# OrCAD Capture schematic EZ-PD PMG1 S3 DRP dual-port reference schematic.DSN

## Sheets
1 01 TABLE AND CONTENTS: title: PMG1-S3 (CYPM1322) 97BGA DRP REF DESIGN; rev: 01; note: XXX-xxxxx-xx
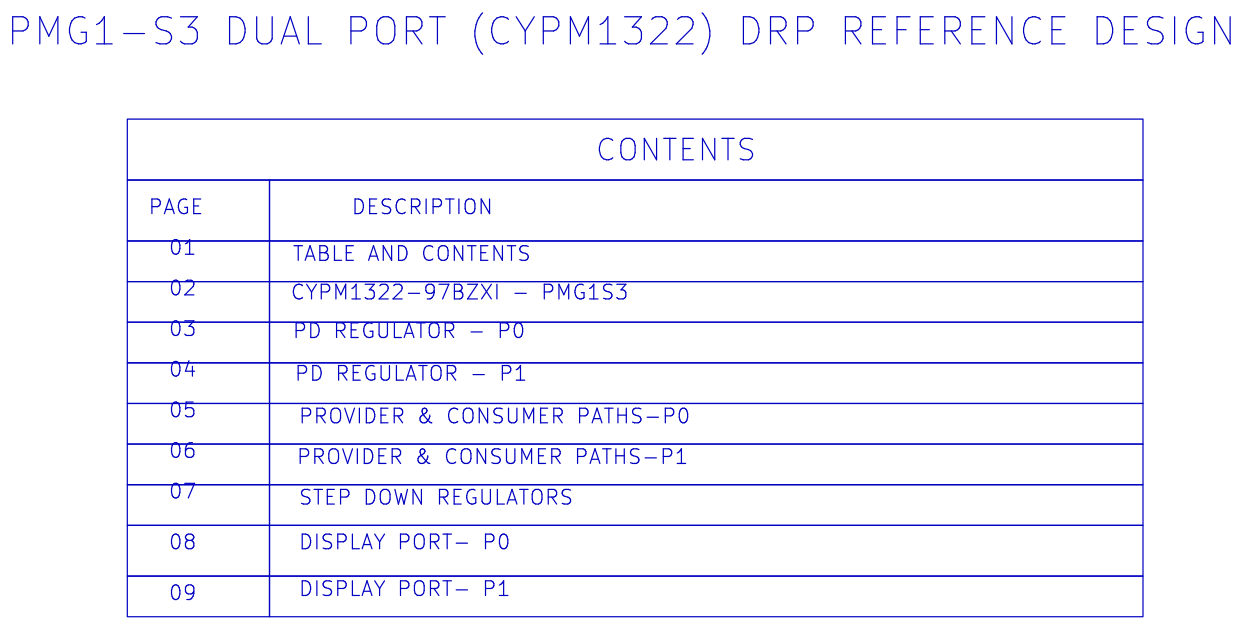
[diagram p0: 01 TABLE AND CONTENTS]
2 02  CYPM1322-97BZXI - PMG1S3: size A4
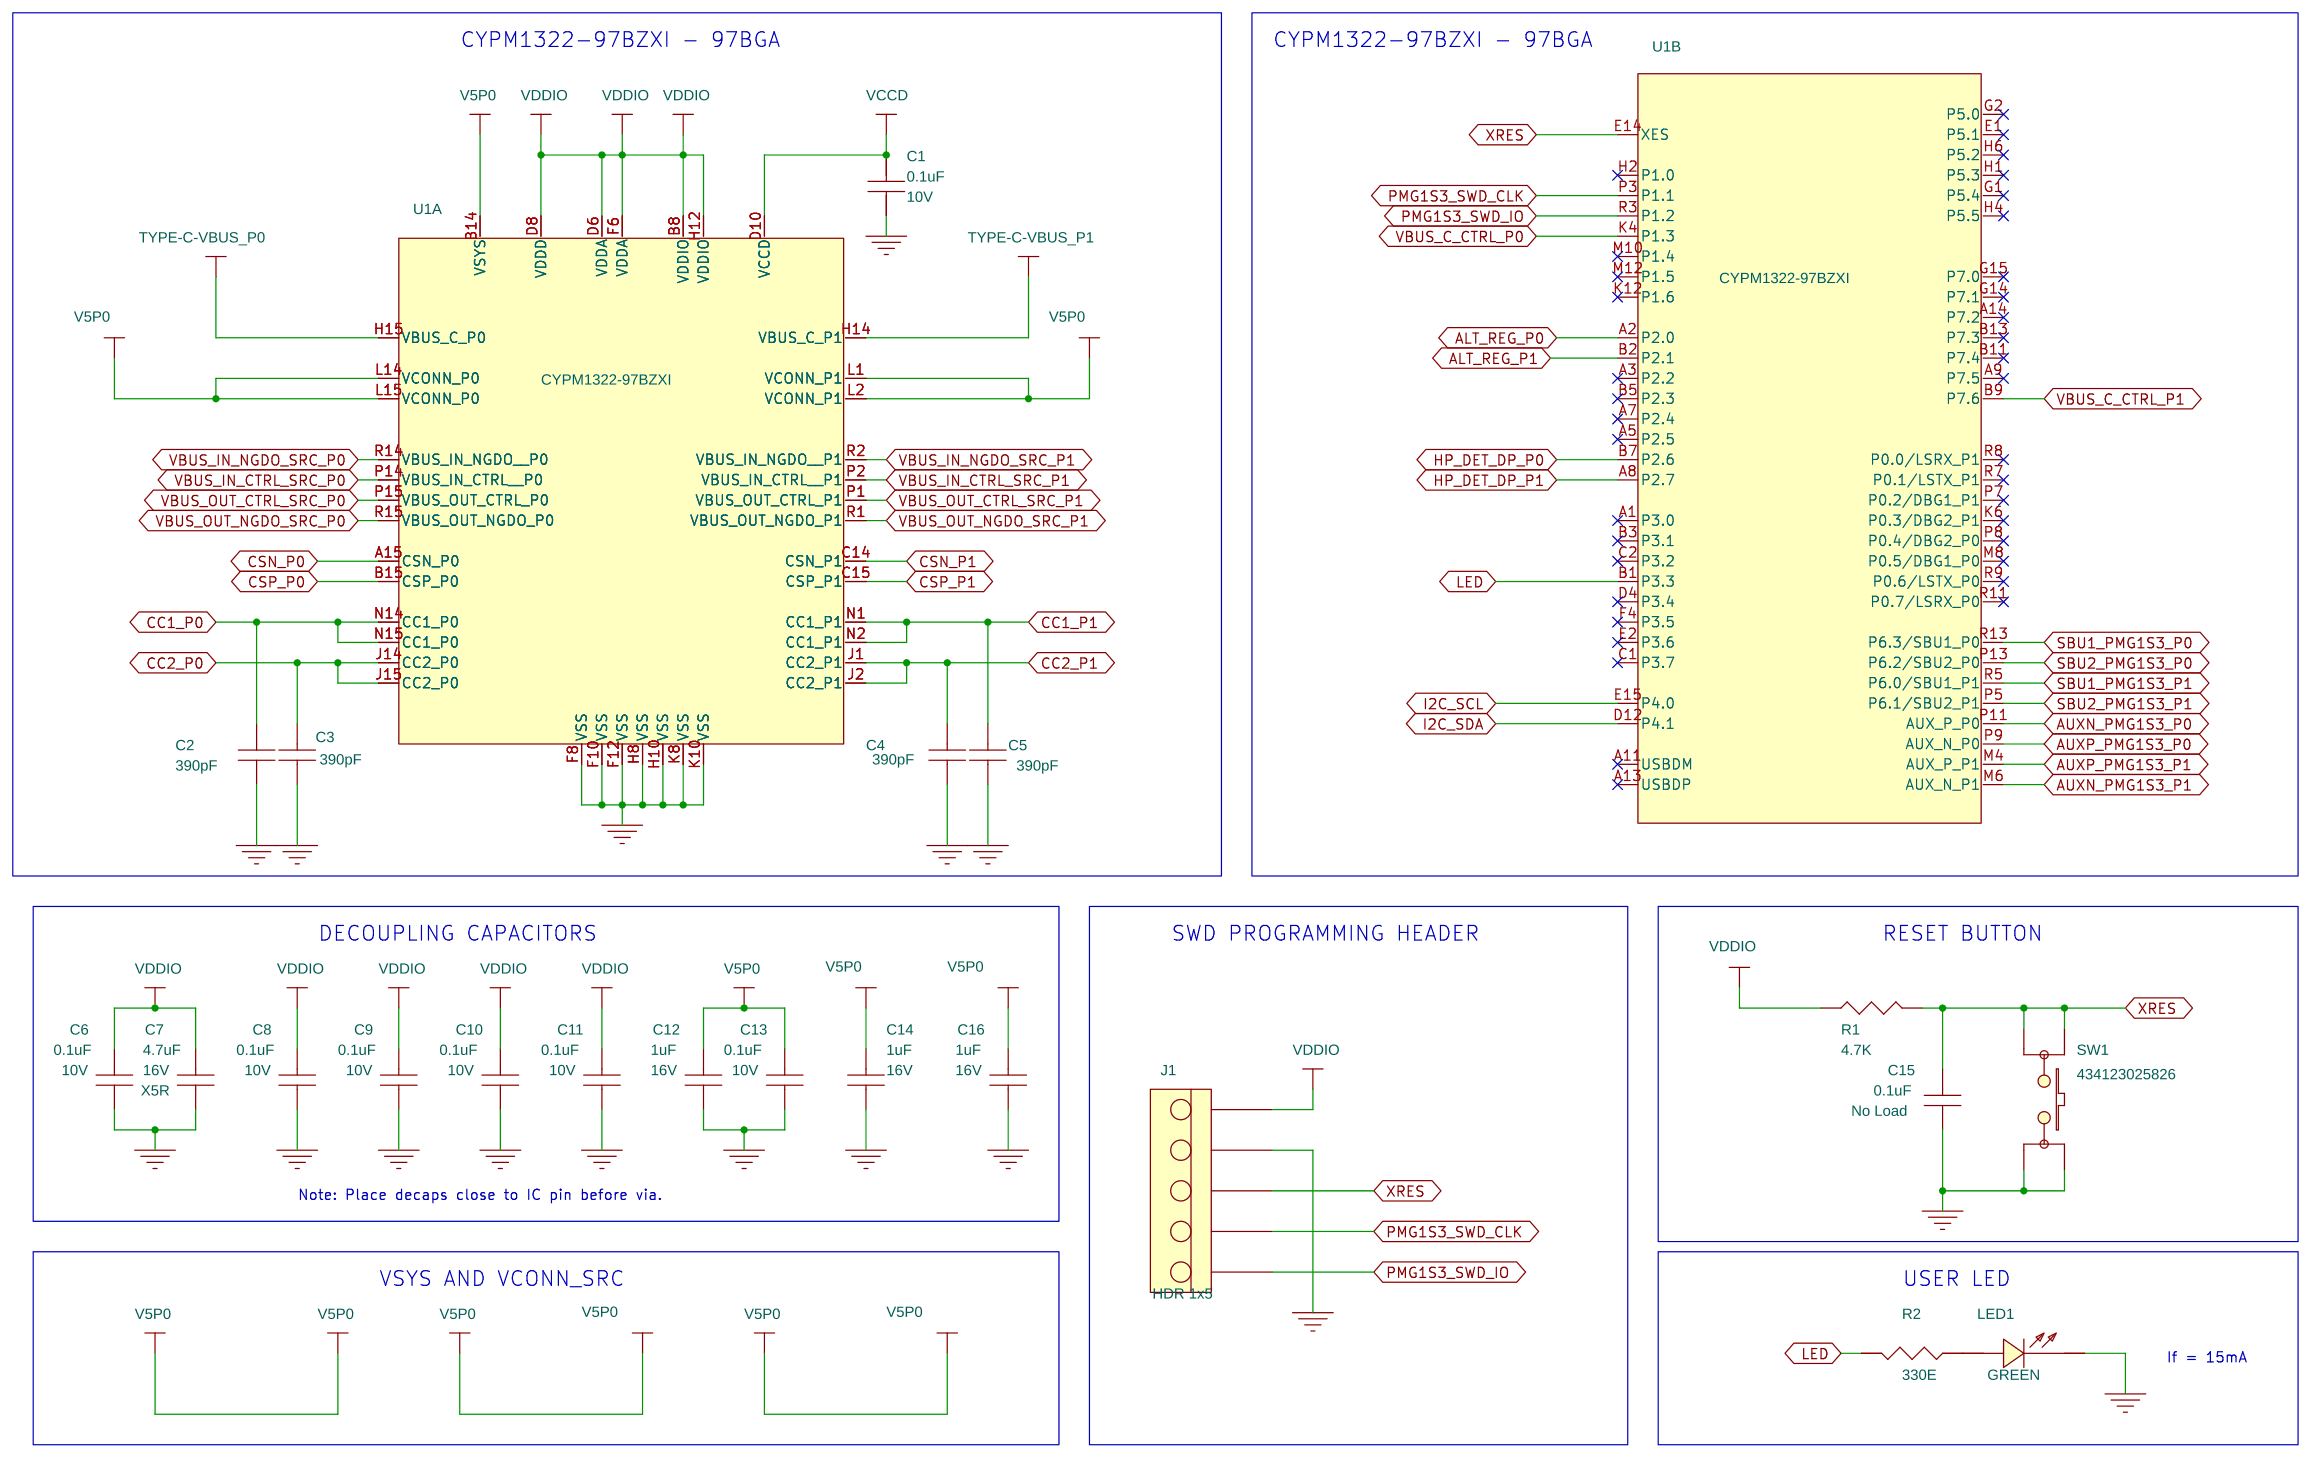
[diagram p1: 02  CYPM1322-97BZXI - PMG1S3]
3 03 PD REGULATOR - P0: size A4
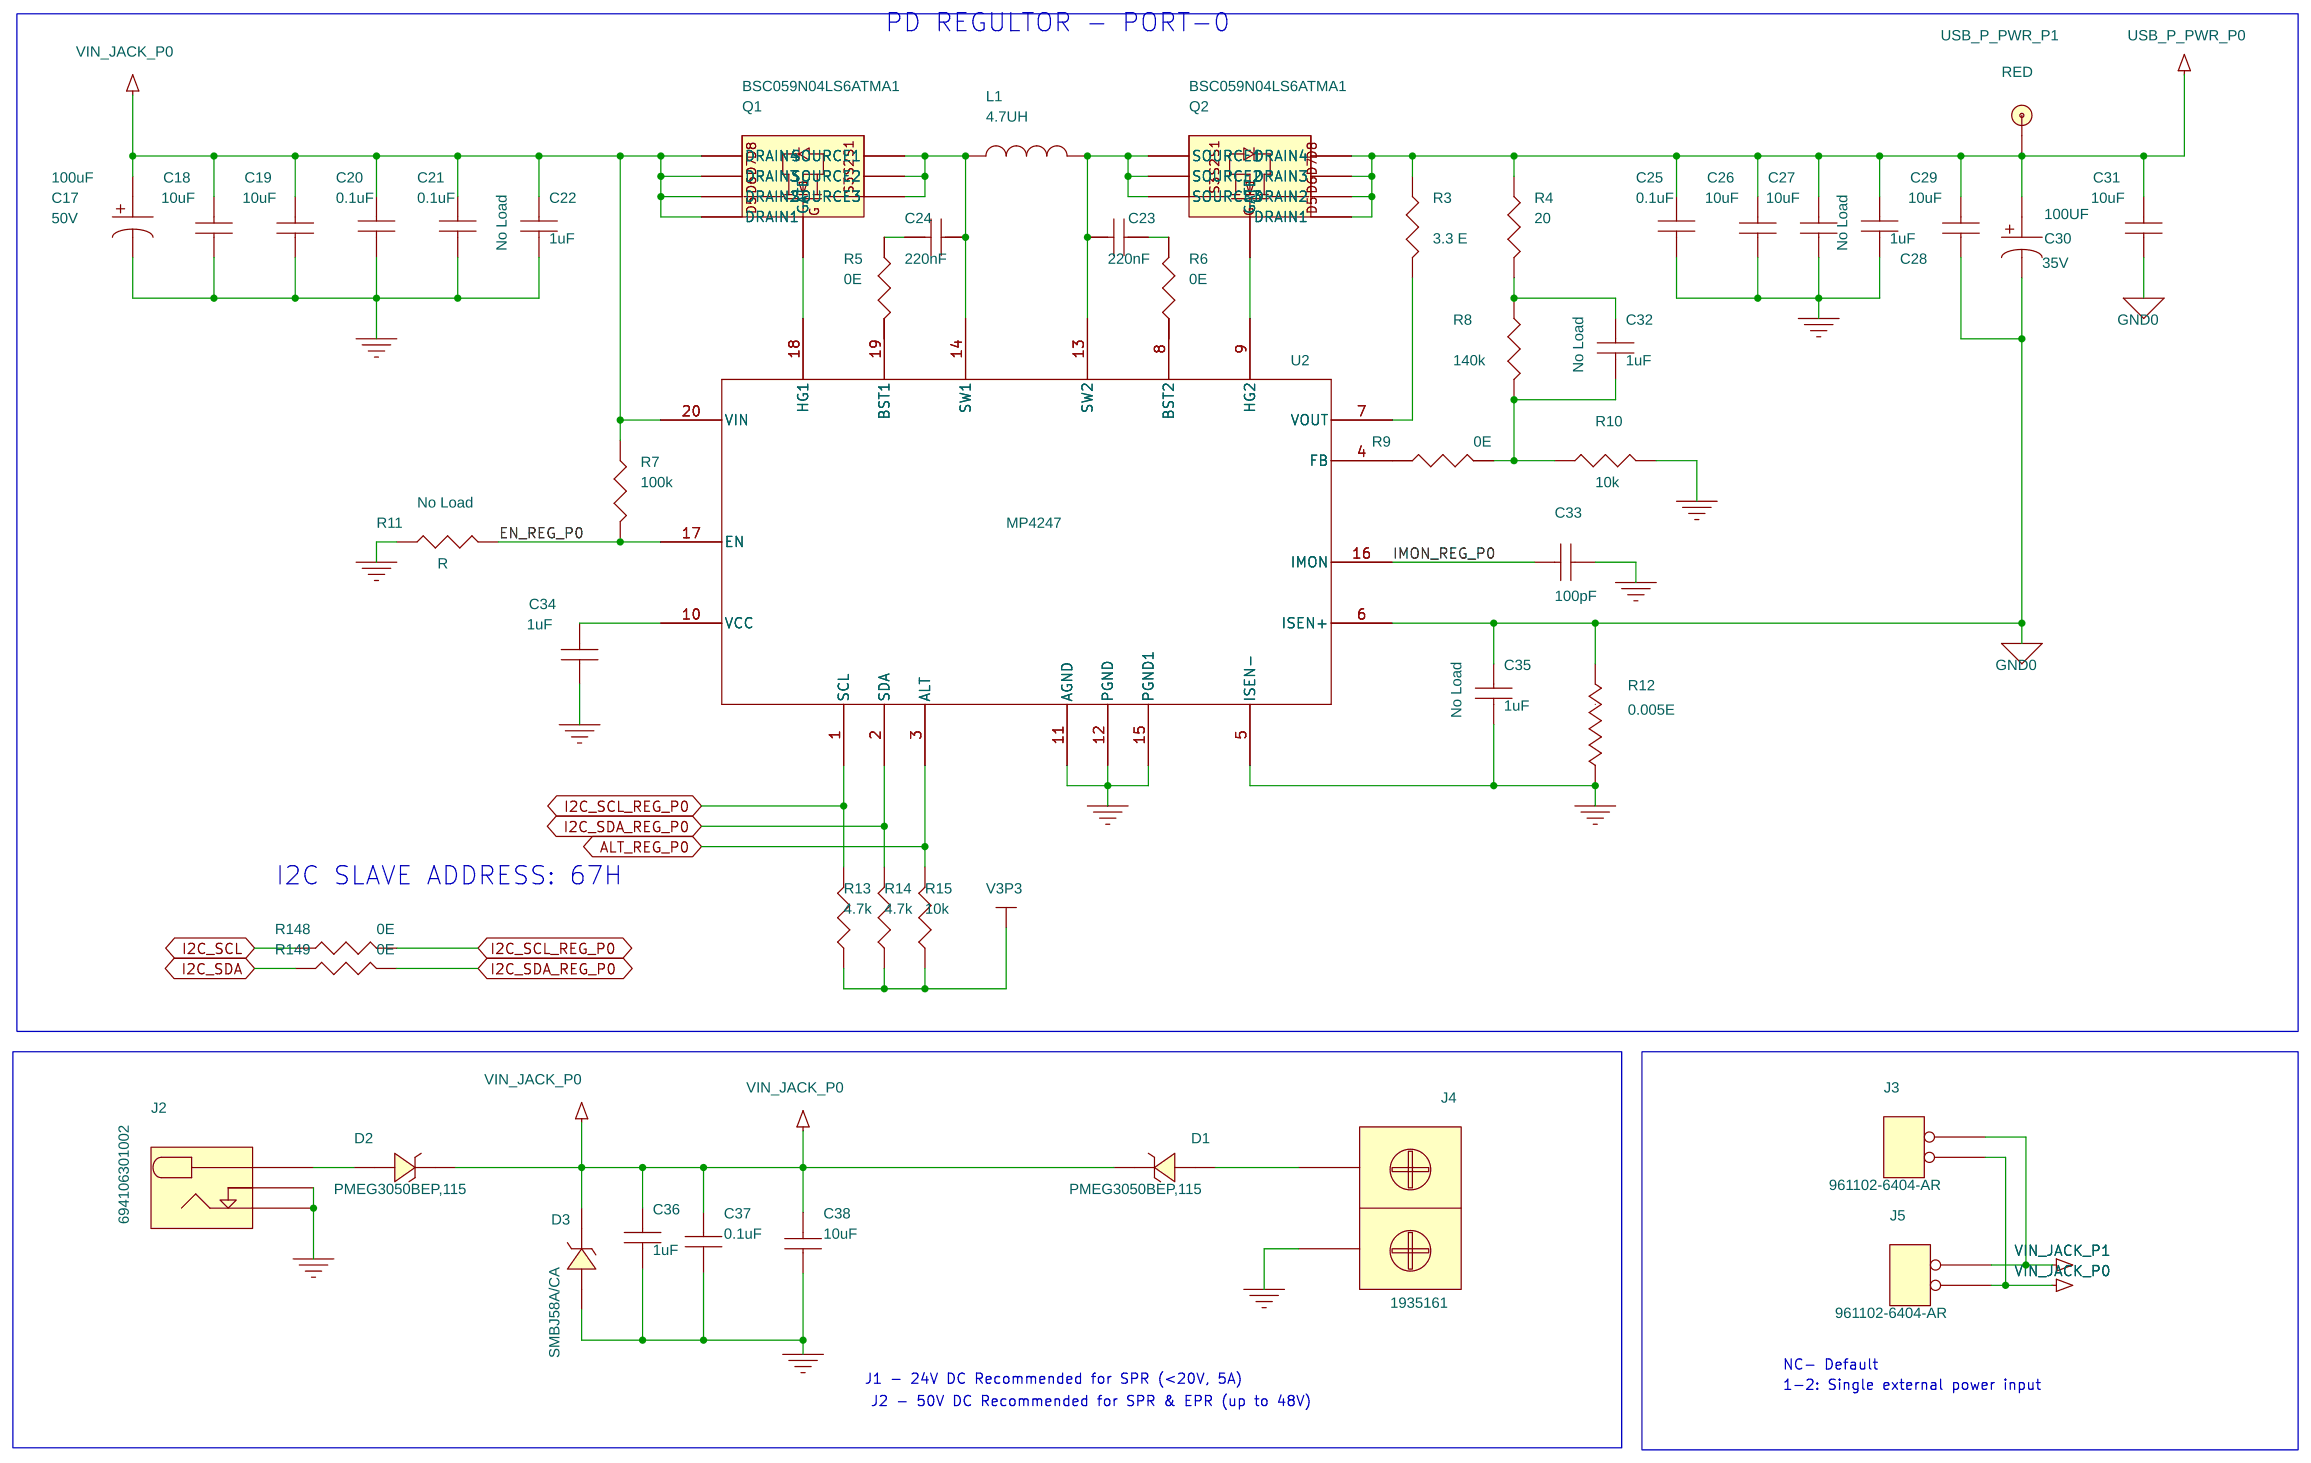
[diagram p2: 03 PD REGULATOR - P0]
4 04 PD REGULATROR - P1: size A4
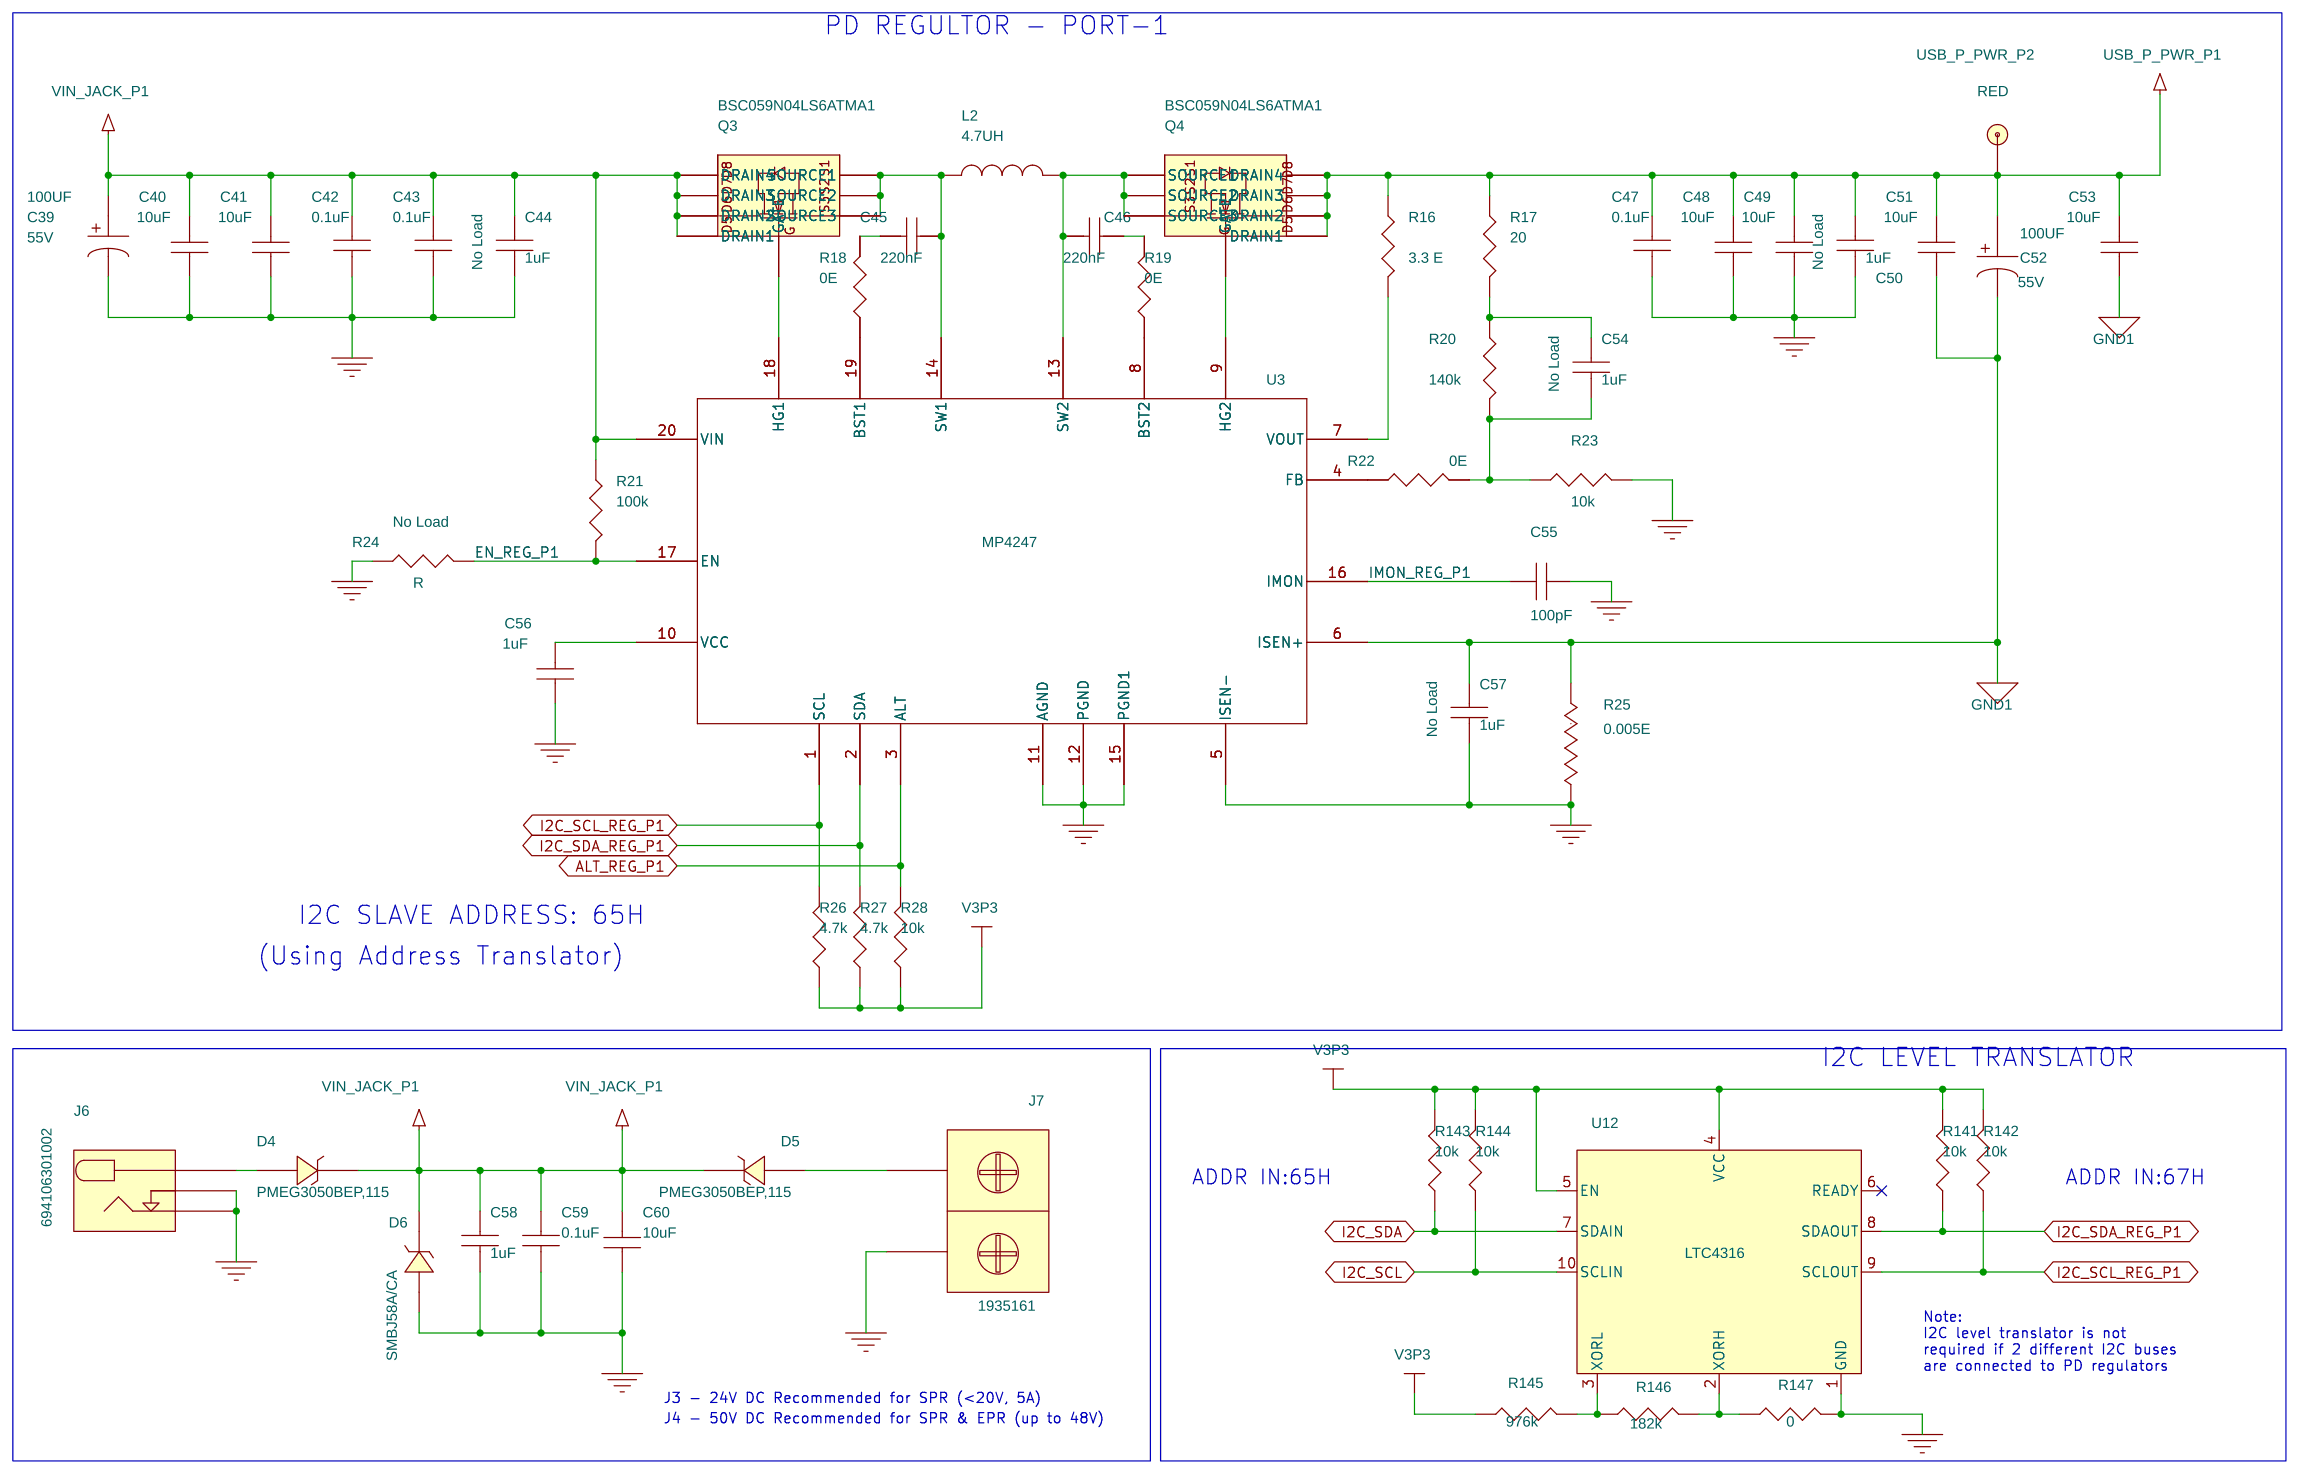
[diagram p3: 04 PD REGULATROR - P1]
5 05 PROVIDER & CONSUMER PATHS-P0: size A4
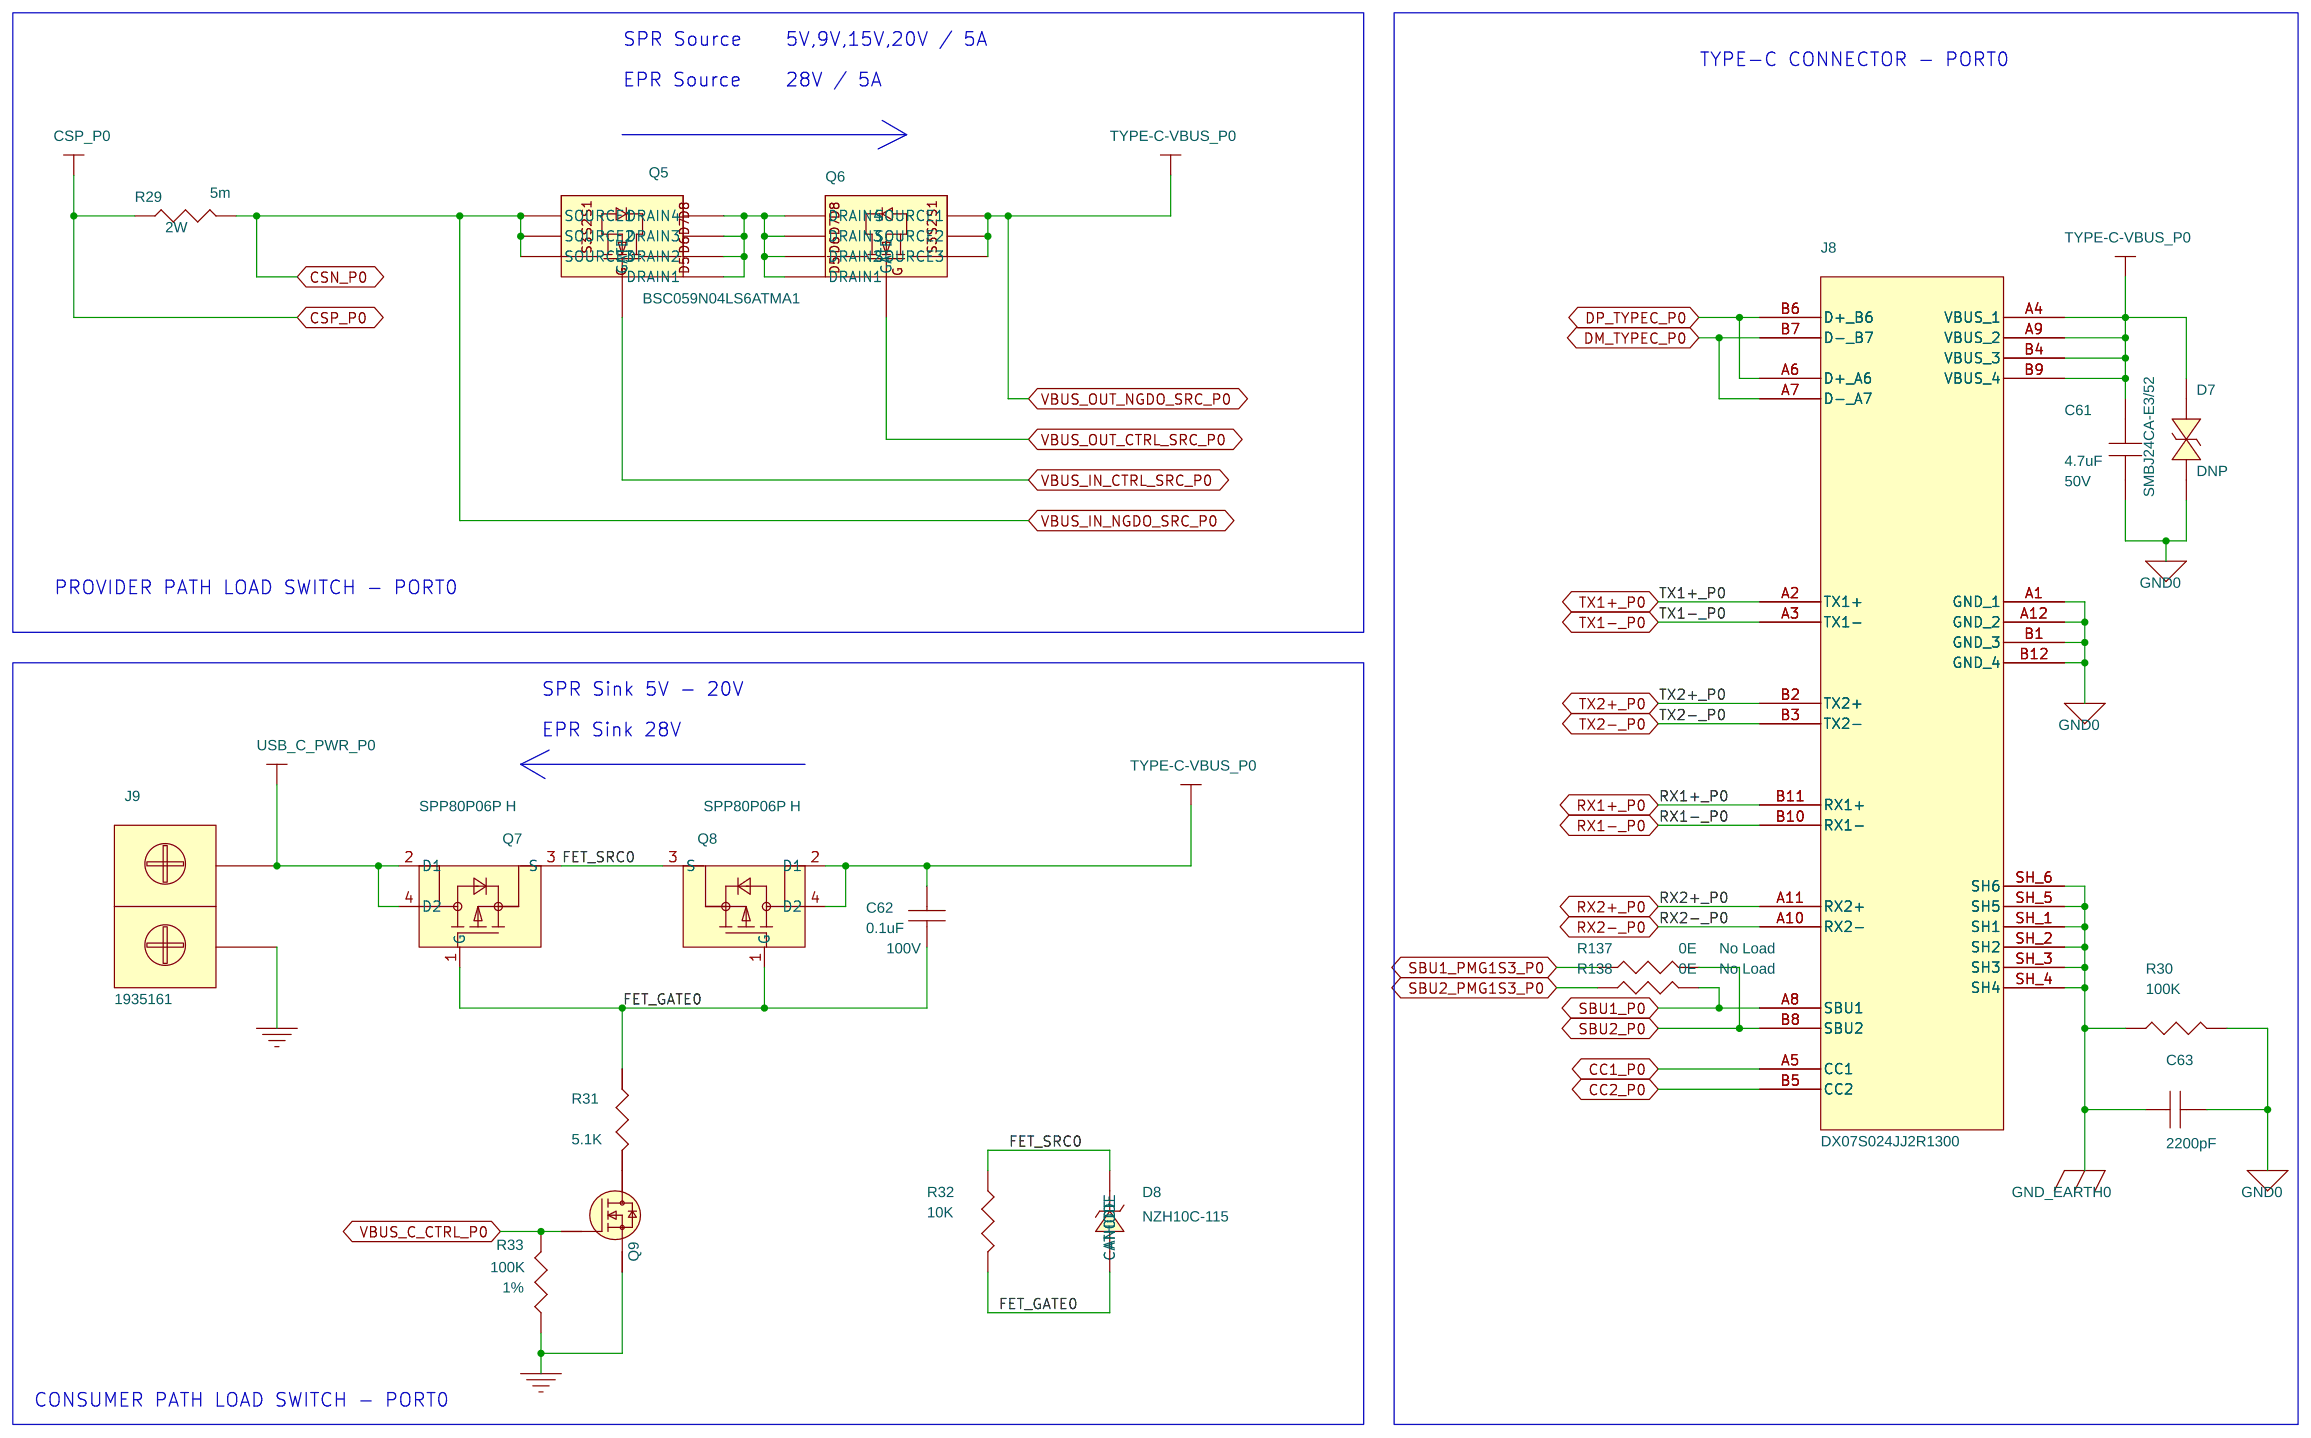
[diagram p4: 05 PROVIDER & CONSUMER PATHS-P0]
6 06 PROVIDER & CONSUMER PATHS-P1: size A4
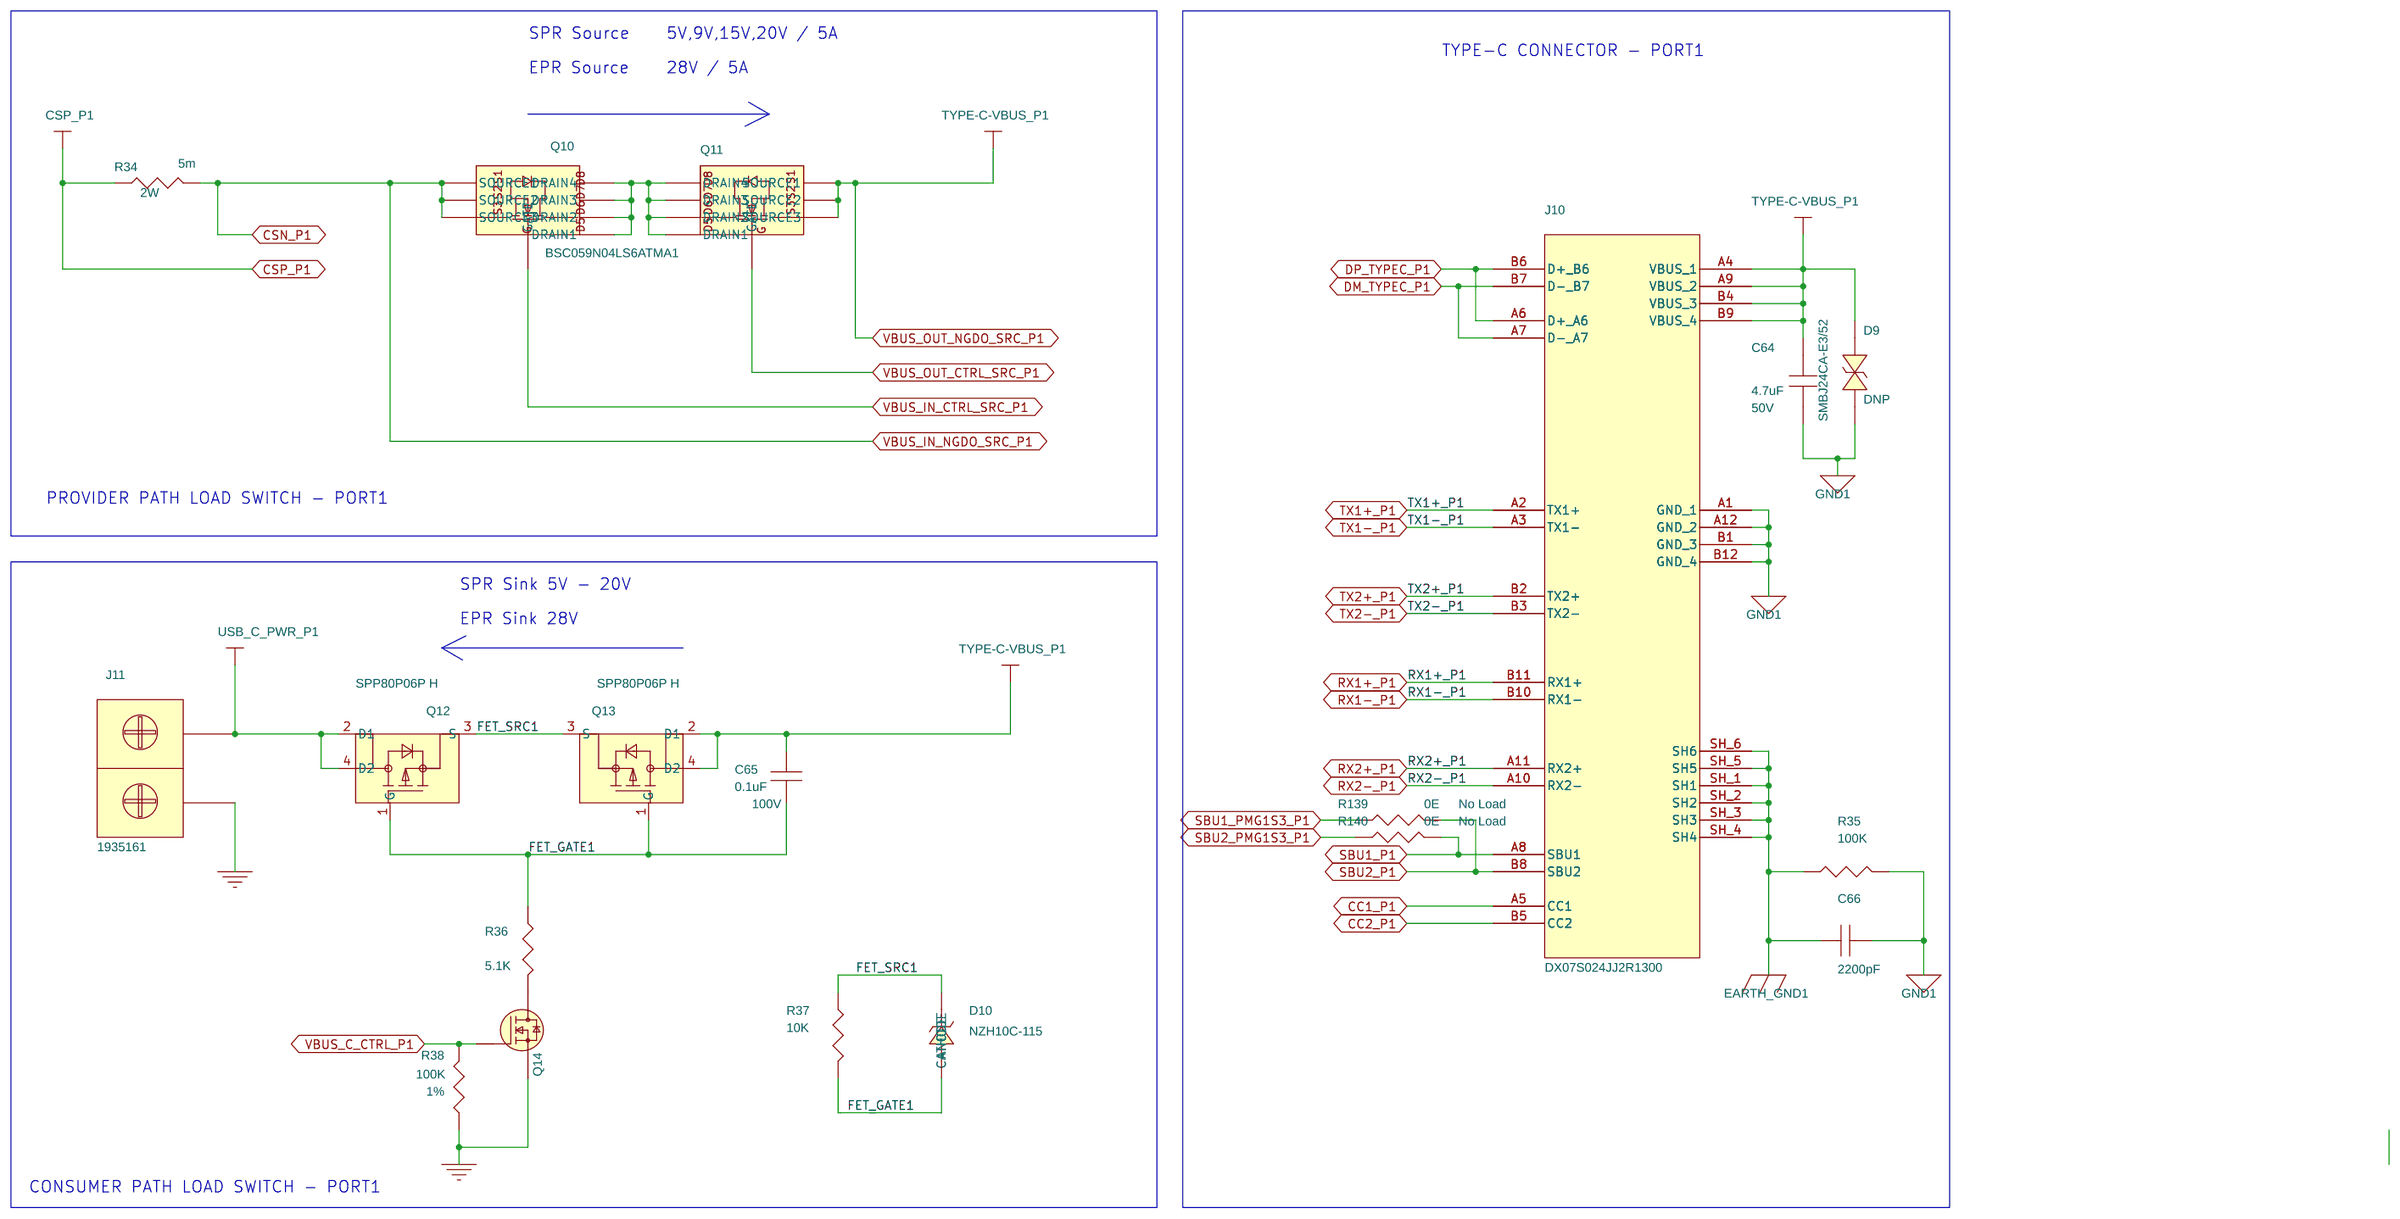
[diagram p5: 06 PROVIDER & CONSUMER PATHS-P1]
7 07 STEP DOWN REGULATORS: size A4
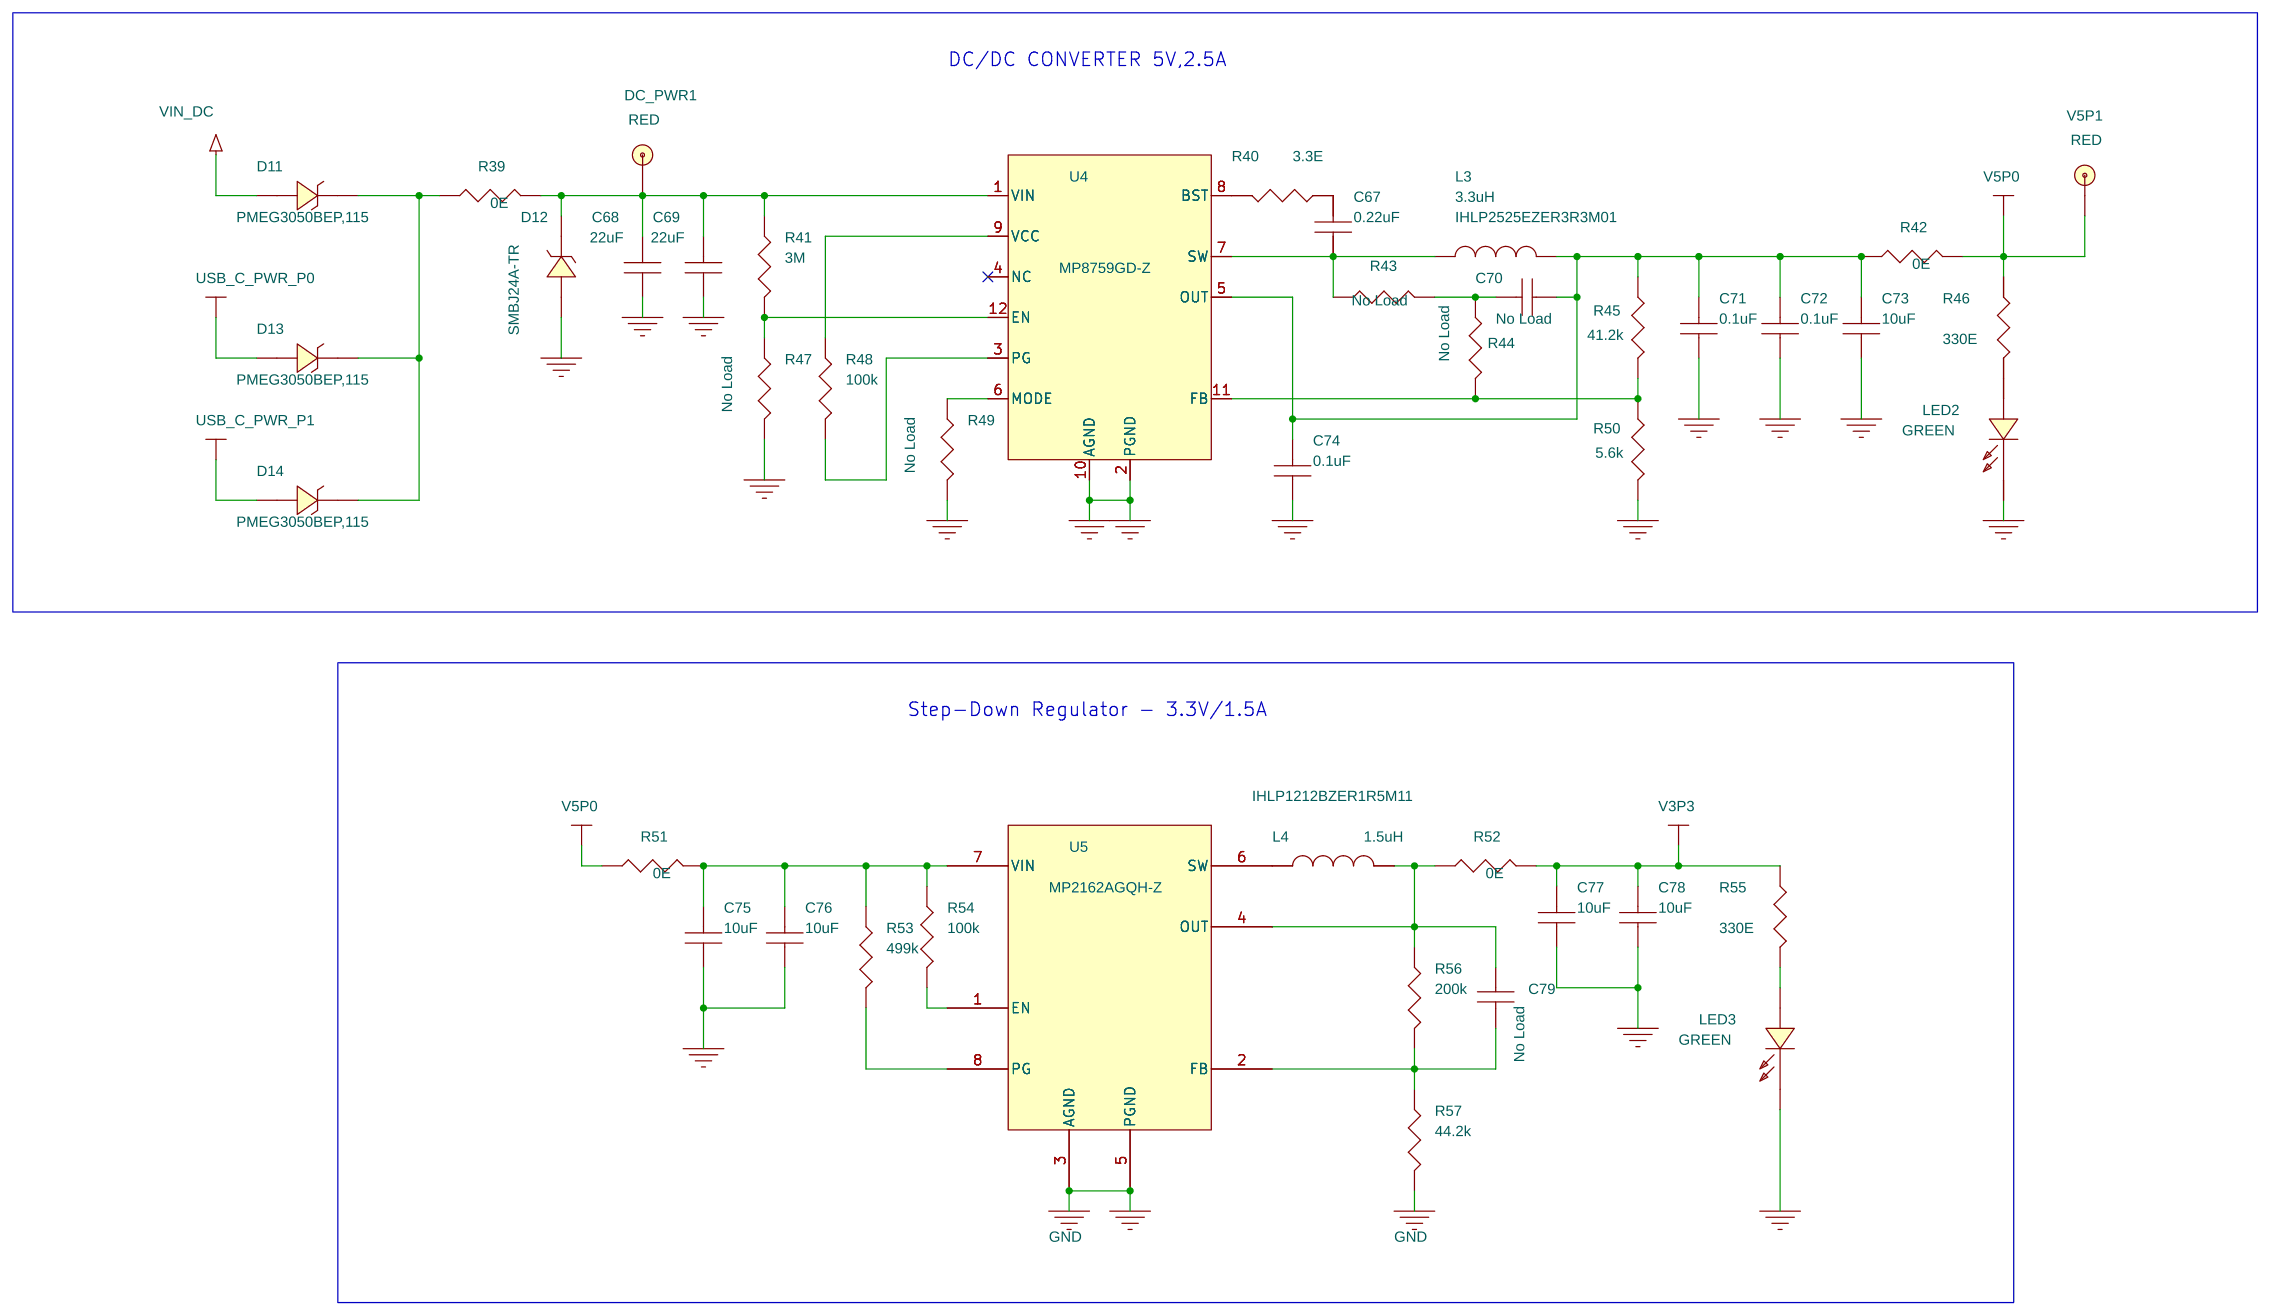
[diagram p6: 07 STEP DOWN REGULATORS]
8 08 DISPLAY PORT- P0: size A4
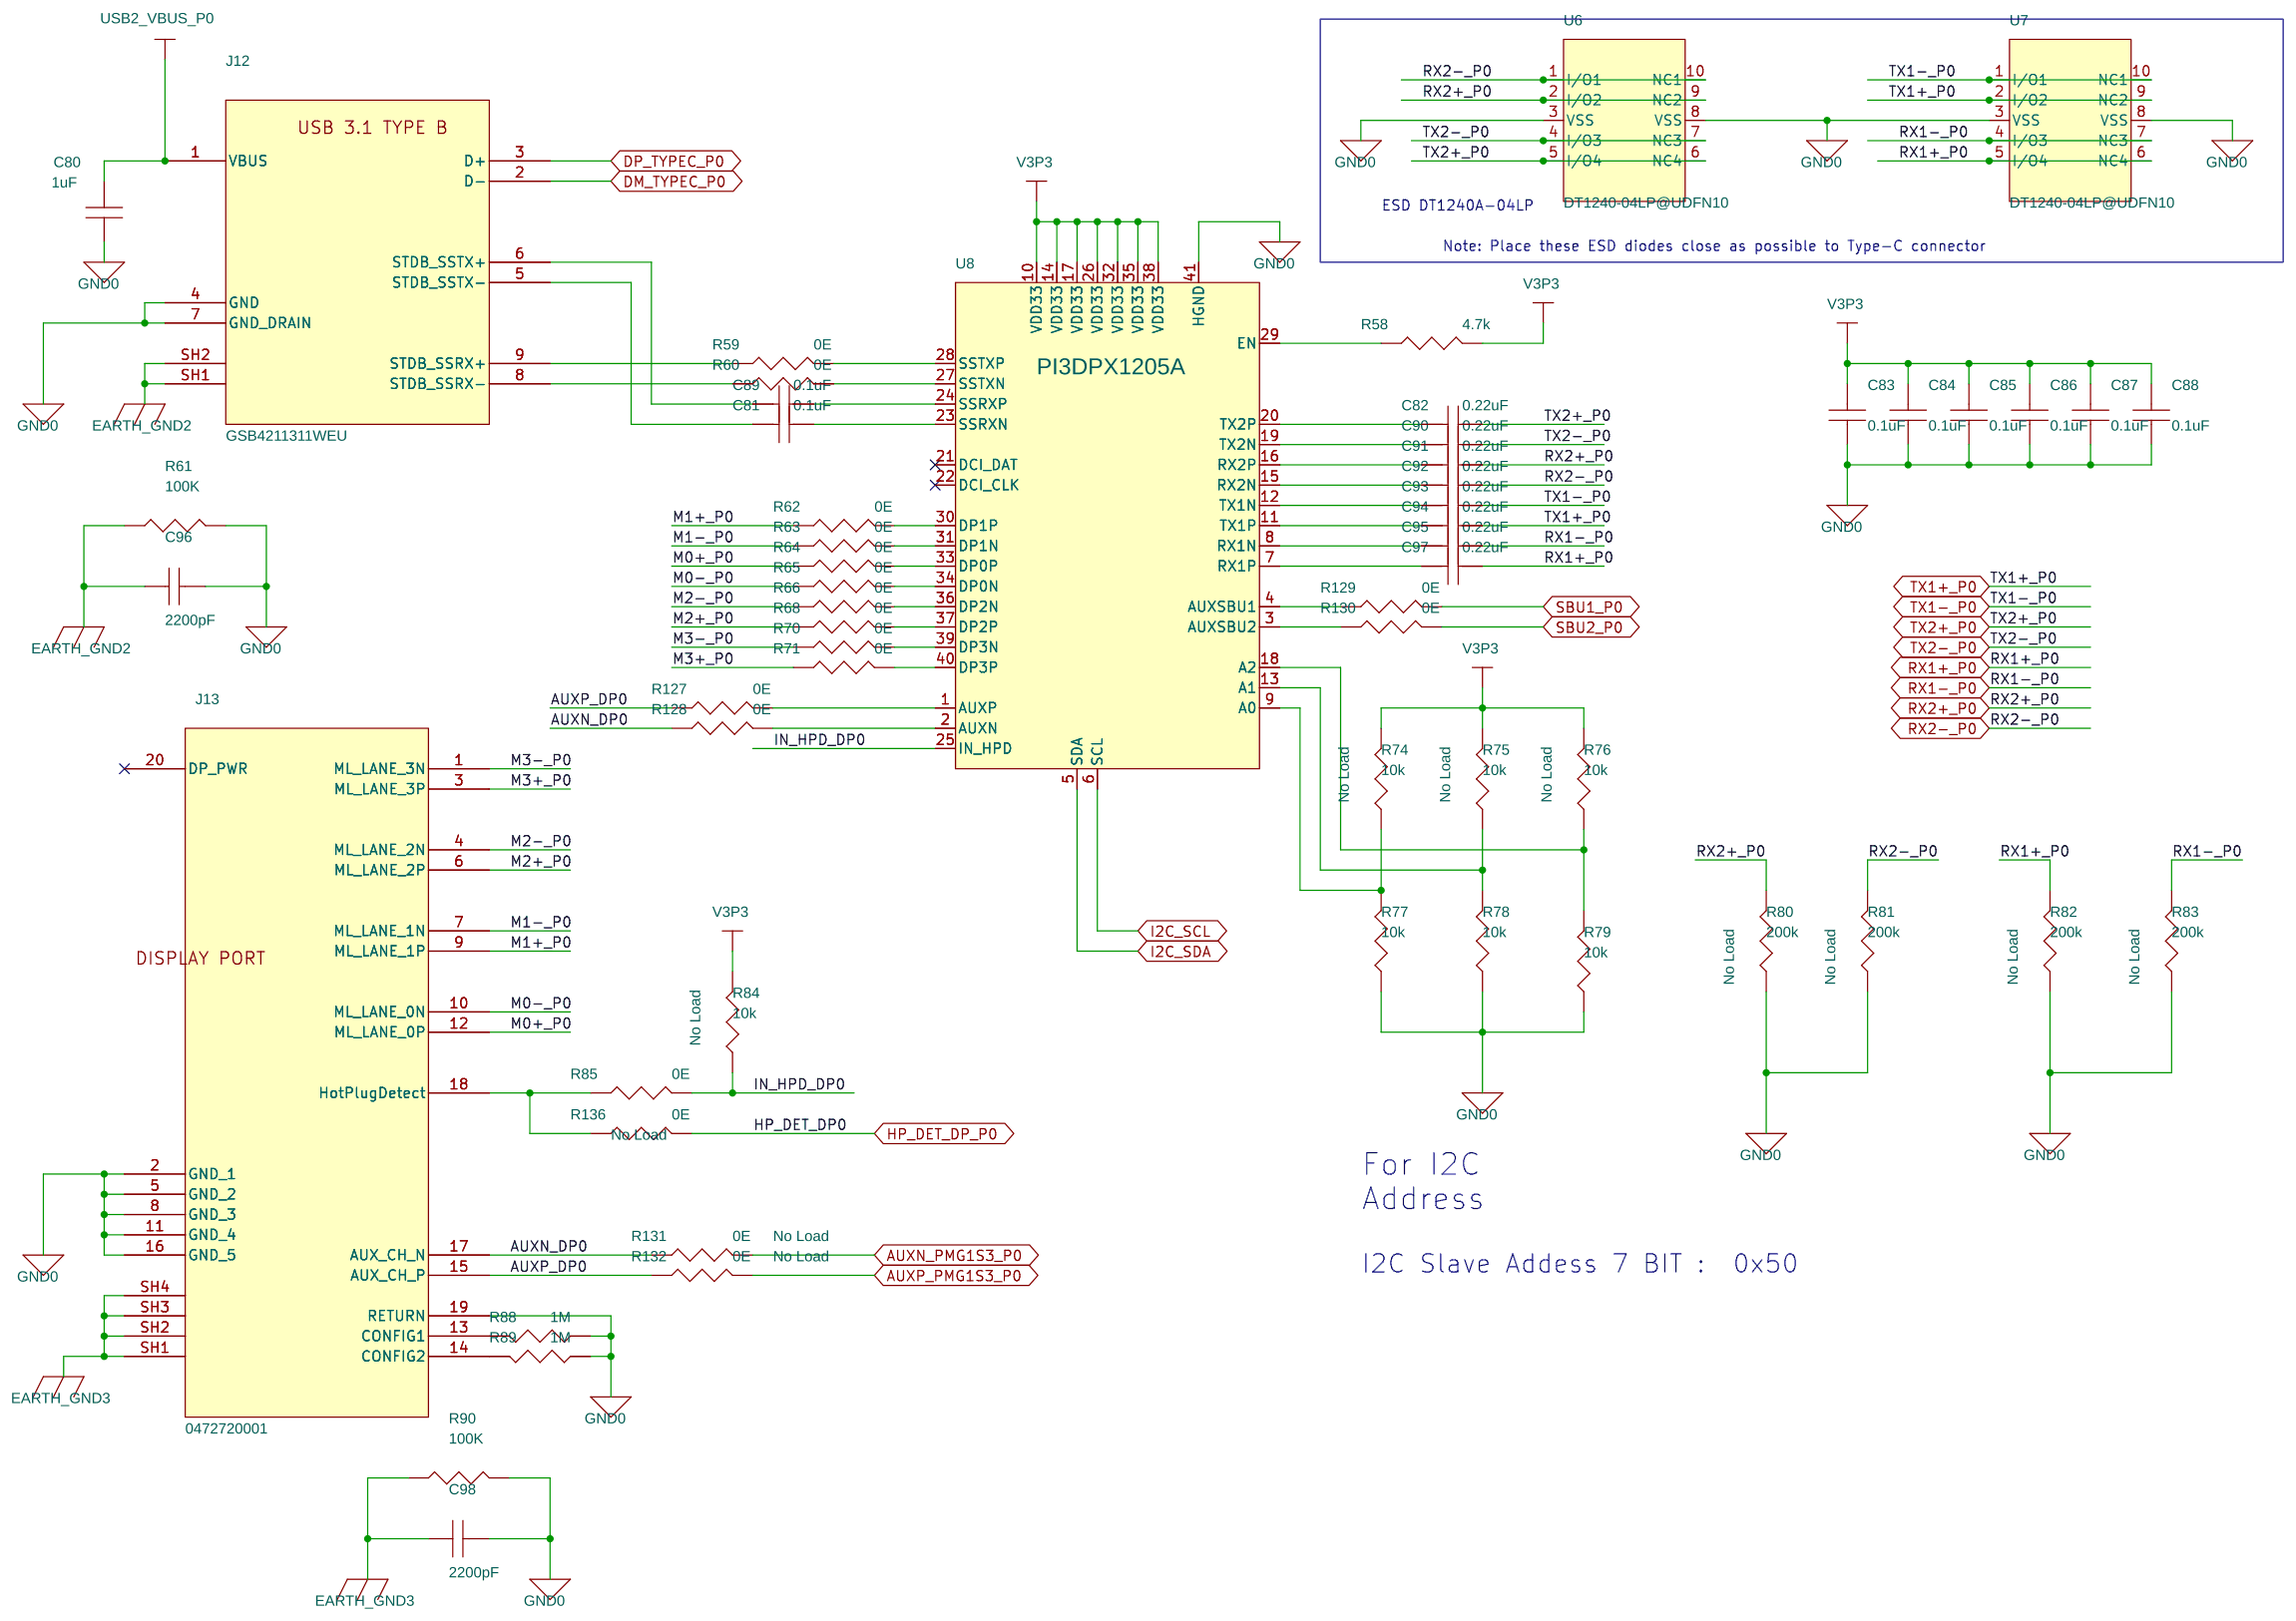
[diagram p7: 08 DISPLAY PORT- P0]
9 09 DISPLAY PORT - P1: size A4
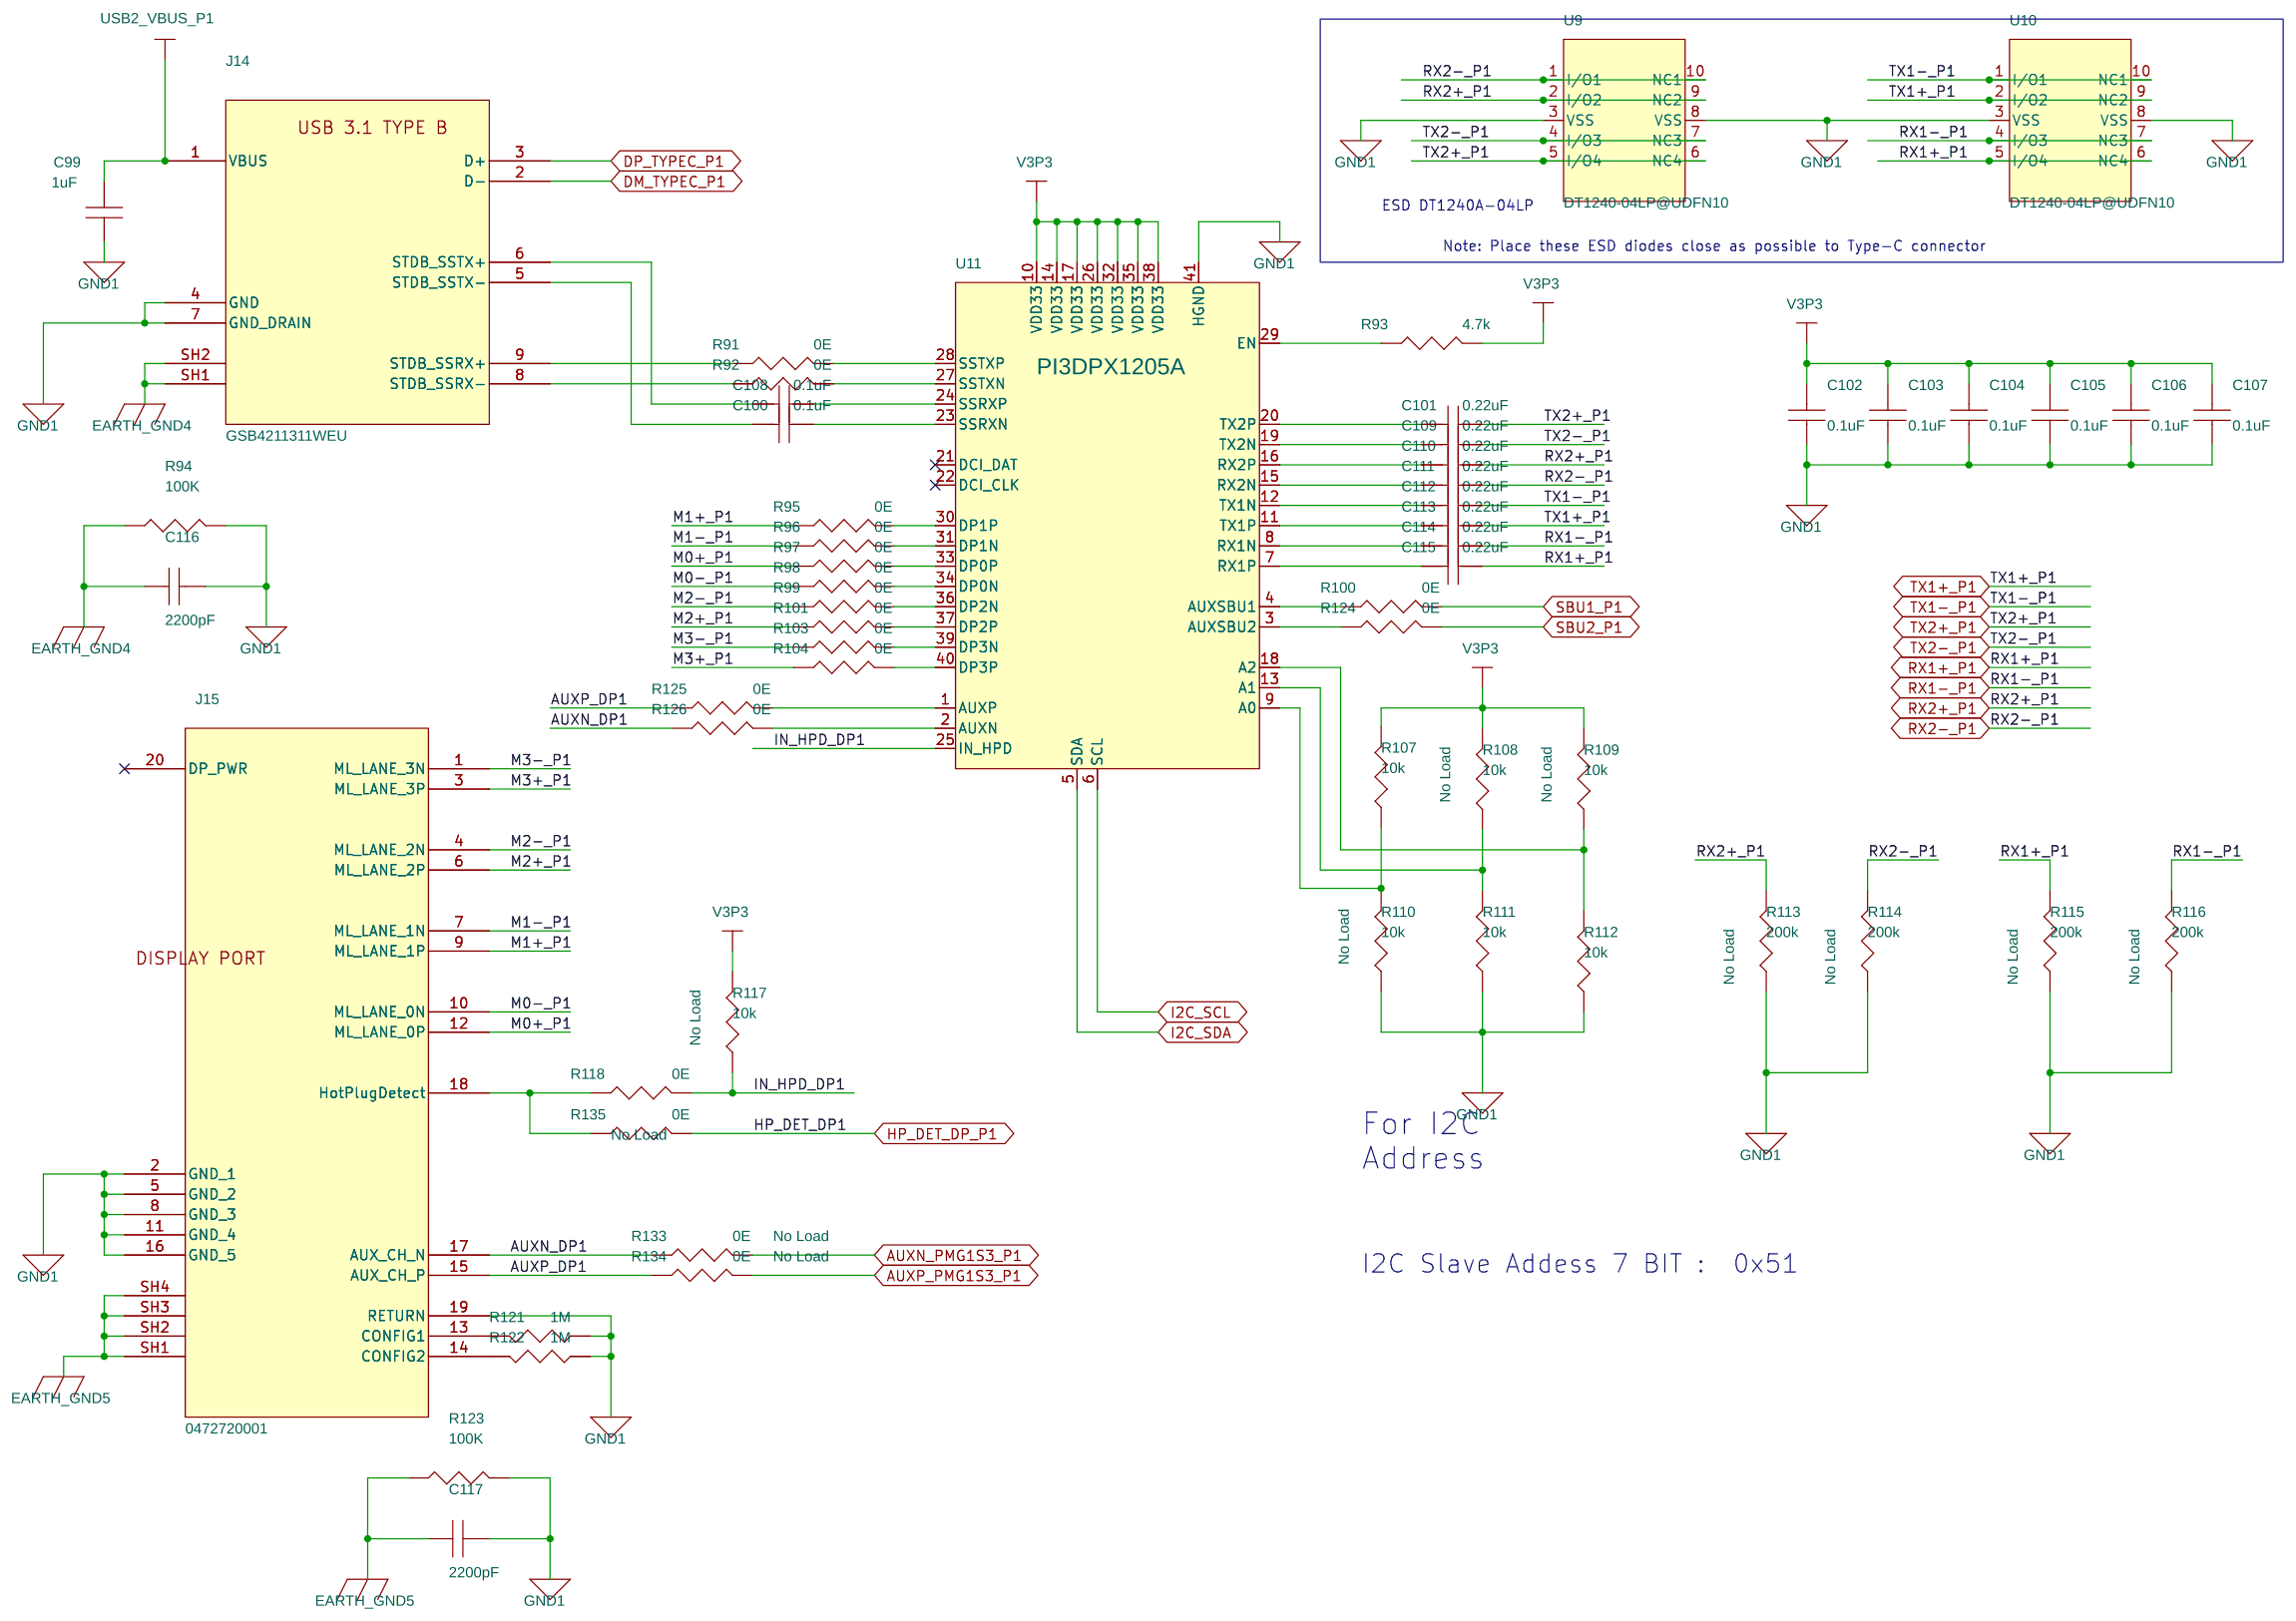
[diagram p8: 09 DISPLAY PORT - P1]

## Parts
sheet 02  CYPM1322-97BZXI - PMG1S3
C1  0.1uF  [CAPC1005_0402N]
C2  390pF  [capc1608x90n_ty]
C3  390pF  [capc1608x90n_ty]
C4  390pF  [capc1608x90n_ty]
C5  390pF  [capc1608x90n_ty]
C6  0.1uF  [CAPC1005_0402N]
C7  4.7uF  [capc1608x90n_ty]
C8  0.1uF  [CAPC1005_0402N]
C9  0.1uF  [CAPC1005_0402N]
C10  0.1uF  [CAPC1005_0402N]
C11  0.1uF  [CAPC1005_0402N]
C12  1uF  [capc1608x90n_ty]
C13  0.1uF  [CAPC1005_0402N]
C14  1uF  [capc1608x90n_ty]
C15  0.1uF  [CAPC1005_0402N]
C16  1uF  [capc1608x90n_ty]
J1  HDR 1x5  [HDR5_KEYED_M]
LED1  GREEN  [LEDC1608X80N_G]
R1  4.7K  [RESC1005_0402M]
R2  330E  [RESC1608X55N_A]
SW1  434123025826  [SW_SKRPACE010]
U1  CYPM1322-97BZXI  (sections A,B)
sheet 03 PD REGULATOR - P0
C17  100uF  [CAPAE830X900D900DD320N]
C18  10uF  [capc2012x70n_murata]
C19  10uF  [capc2012x70n_murata]
C20  0.1uF  [capc1608x90n_ty]
C21  0.1uF  [capc1608x90n_ty]
C22  1uF  [capc1608x90n_ty]
C23  220nF  [capc1608x90n_ty]
C24  220nF  [capc1608x90n_ty]
C25  0.1uF  [capc1608x90n_ty]
C26  10uF  [capc2012x70n_murata]
C27  10uF  [capc2012x70n_murata]
C28  1uF  [capc1608x90n_ty]
C29  10uF  [capc2012x70n_murata]
C30  100UF  [CAPAE830X900D900DD320N]
C31  10uF  [capc2012x70n_murata]
C32  1uF  [capc1608x90n_ty]
C33  100pF  [capc1608x90n_ty]
C34  1uF  [capc1005x56n_cyps]
C35  1uF  [capc1608x90n_ty]
C36  1uF  [capc1608x90n_ty]
C37  0.1uF  [capc1608x90n_ty]
C38  10uF  [capc3225x280n_tdk]
D1  PMEG3050BEP,115  [SOD128]
D2  PMEG3050BEP,115  [SOD128]
D3  SMBJ58A/CA  [SMBJ24A-TR]
J2  694106301002  [wurth_694106301002]
J3  961102-6404-AR  [hdr2x1]
J4  1935161  [1935161]
J5  961102-6404-AR  [hdr2x1]
L1  4.7UH  [IND_MPL-AY1050-4R7]
Q1  BSC059N04LS6ATMA1  [SON127P600X500X110-8N]
Q2  BSC059N04LS6ATMA1  [SON127P600X500X110-8N]
R3  3.3 E  [resc1608x55n_pec]
R4  20  [resc1608x55n_pec]
R5  0E  [resc1608x55n_pec]
R6  0E  [resc1608x55n_pec]
R7  100k  [resc1608x55n_pec]
R8  140k  [resc1608x55n_pec]
R9  0E  [resc1005x40n_pec]
R10  10k  [resc1608x55n_pec]
R11  R  [resc1608x55n_pec]
R12  0.005E  [WSL1206]
R13  4.7k  [resc1005x40n_pec]
R14  4.7k  [resc1005x40n_pec]
R15  10k  [resc1608x55n_pec]
R148  0E  [resc1005x40n_pec]
R149  0E  [resc1005x40n_pec]
U2  MP4247  [QFN50P300X500X100-20N]
USB_P_PWR_P1  RED  [TP-43R_S]
sheet 04 PD REGULATROR - P1
C39  100UF  [CAPAE830X900D900DD320N]
C40  10uF  [capc2012x70n_murata]
C41  10uF  [capc2012x70n_murata]
C42  0.1uF  [capc1608x90n_ty]
C43  0.1uF  [capc1608x90n_ty]
C44  1uF  [capc1608x90n_ty]
C45  220nF  [capc1608x90n_ty]
C46  220nF  [capc1608x90n_ty]
C47  0.1uF  [capc1608x90n_ty]
C48  10uF  [capc2012x70n_murata]
C49  10uF  [capc2012x70n_murata]
C50  1uF  [capc1608x90n_ty]
C51  10uF  [capc2012x70n_murata]
C52  100UF  [CAPAE830X900D900DD320N]
C53  10uF  [capc2012x70n_murata]
C54  1uF  [capc1608x90n_ty]
C55  100pF  [capc1608x90n_ty]
C56  1uF  [capc1005x56n_cyps]
C57  1uF  [capc1608x90n_ty]
C58  1uF  [capc1608x90n_ty]
C59  0.1uF  [capc1608x90n_ty]
C60  10uF  [capc3225x280n_tdk]
D4  PMEG3050BEP,115  [SOD128]
D5  PMEG3050BEP,115  [SOD128]
D6  SMBJ58A/CA  [SMBJ24A-TR]
J6  694106301002  [wurth_694106301002]
J7  1935161  [1935161]
L2  4.7UH  [IND_MPL-AY1050-4R7]
Q3  BSC059N04LS6ATMA1  [SON127P600X500X110-8N]
Q4  BSC059N04LS6ATMA1  [SON127P600X500X110-8N]
R16  3.3 E  [resc1608x55n_pec]
R17  20  [resc1608x55n_pec]
R18  0E  [resc1608x55n_pec]
R19  0E  [resc1608x55n_pec]
R20  140k  [resc1608x55n_pec]
R21  100k  [resc1608x55n_pec]
R22  0E  [resc1005x40n_pec]
R23  10k  [resc1608x55n_pec]
R24  R  [resc1608x55n_pec]
R25  0.005E  [WSL1206]
R26  4.7k  [resc1005x40n_pec]
R27  4.7k  [resc1005x40n_pec]
R28  10k  [resc1608x55n_pec]
R141  10k  [resc1608x55n_pec]
R142  10k  [resc1608x55n_pec]
R143  10k  [resc1608x55n_pec]
R144  10k  [resc1608x55n_pec]
R145  976k  [resc1608x55n_pec]
R146  182k  [resc1608x55n_pec]
R147  0  [resc1005x40n_pec]
U3  MP4247  [QFN50P300X500X100-20N]
U12  LTC4316
USB_P_PWR_P2  RED  [TP-43R_S]
sheet 05 PROVIDER & CONSUMER PATHS-P0
C61  4.7uF  [capc3225x280n_tdk]
C62  0.1uF  [capc1005x56n_cyps]
C63  2200pF  [C1808]
D7  SMBJ24CA-E3/52  [SMBJ24CA_3P679_2H44]
D8  NZH10C-115  [SOD123F_NZH10C-115]
J8  DX07S024JJ2R1300  [USB-PD_TYPE-C]
J9  1935161  [1935161]
Q5  BSC059N04LS6ATMA1  [BSC059N04LS6ATMA1]
Q6  BSC059N04LS6ATMA1  [BSC059N04LS6ATMA1]
Q7  SPP80P06P H
Q8  SPP80P06P H
Q9  2N7002LT1G  [SOT23_2N7002LT1G]
R29  5m  [RESC6432X69N]
R30  100K  [resc1005x40n_pec]
R31  5.1K  [resc1005x40n_pec]
R32  10K  [resc1005x40n_pec]
R33  100K  [resc1608x55n_pec]
R137  0E  [resc1005x40n_pec]
R138  0E  [resc1005x40n_pec]
sheet 06 PROVIDER & CONSUMER PATHS-P1
C64  4.7uF  [capc3225x280n_tdk]
C65  0.1uF  [capc1005x56n_cyps]
C66  2200pF  [C1808]
D9  SMBJ24CA-E3/52  [SMBJ24CA_3P679_2H44]
D10  NZH10C-115  [SOD123F_NZH10C-115]
J10  DX07S024JJ2R1300  [USB-PD_TYPE-C]
J11  1935161  [1935161]
Q10  BSC059N04LS6ATMA1  [BSC059N04LS6ATMA1]
Q11  BSC059N04LS6ATMA1  [BSC059N04LS6ATMA1]
Q12  SPP80P06P H
Q13  SPP80P06P H
Q14  2N7002LT1G  [SOT23_2N7002LT1G]
R34  5m  [RESC6432X69N]
R35  100K  [resc1005x40n_pec]
R36  5.1K  [resc1005x40n_pec]
R37  10K  [resc1005x40n_pec]
R38  100K  [resc1608x55n_pec]
R139  0E  [resc1005x40n_pec]
R140  0E  [resc1005x40n_pec]
sheet 07 STEP DOWN REGULATORS
C67  0.22uF  [capc1608x90n_ty]
C68  22uF  [CAPC3216X180N]
C69  22uF  [CAPC3216X180N]
C70  0.22uF  [capc1608x90n_ty]
C71  0.1uF  [capc1608x90n_ty]
C72  0.1uF  [capc1608x90n_ty]
C73  10uF  [capc1608x90n_ty]
C74  0.1uF  [capc1608x90n_ty]
C75  10uF  [capc1608x90n_ty]
C76  10uF  [capc1608x90n_ty]
C77  10uF  [capc1608x90n_ty]
C78  10uF  [capc1608x90n_ty]
C79  0.22uF  [capc1608x90n_ty]
D11  PMEG3050BEP,115  [SOD128]
D12  SMBJ24A-TR  [SMBJ24A-TR]
D13  PMEG3050BEP,115  [SOD128]
D14  PMEG3050BEP,115  [SOD128]
DC_PWR1  RED  [TP-43R_S]
L3  3.3uH  [IHLP2525EZER3R3M01]
L4  1.5uH  [IHLP1212BZER1R5M11]
LED2  GREEN  [LEDC1608X80N_G]
LED3  GREEN  [LEDC1608X80N_G]
R39  0E  [RESC2012X70N_PEC]
R40  3.3E  [resc1608x55n_pec]
R41  3M  [resc1005x40n_pec]
R42  0E  [RESC2012X70N_PEC]
R43  0E  [resc1608x55n_pec]
R44  0E  [resc1608x55n_pec]
R45  41.2k  [resc1608x55n_pec]
R46  330E  [resc1608x55n_pec]
R47  R  [resc1005x40n_pec]
R48  100k  [resc1005x40n_pec]
R49  R  [resc1005x40n_pec]
R50  5.6k  [resc1608x55n_pec]
R51  0E  [RESC2012X70N_PEC]
R52  0E  [RESC2012X70N_PEC]
R53  499k  [resc1005x40n_pec]
R54  100k  [resc1005x40n_pec]
R55  330E  [resc1608x55n_pec]
R56  200k  [resc1005x40n_pec]
R57  44.2k  [resc1005x40n_pec]
U4  MP8759GD-Z  [QFN12_2X3mm]
U5  MP2162AGQH-Z  [QFN8_2P0X1P5]
V5P1  RED  [TP-43R_S]
sheet 08 DISPLAY PORT- P0
C80  1uF  [capc1005x56n_cyps]
C81  0.1uF  [capc1005x56n_cyps]
C82  0.22uF  [capc1005x56n_cyps]
C83  0.1uF  [capc1005x56n_cyps]
C84  0.1uF  [capc1005x56n_cyps]
C85  0.1uF  [capc1005x56n_cyps]
C86  0.1uF  [capc1005x56n_cyps]
C87  0.1uF  [capc1005x56n_cyps]
C88  0.1uF  [capc1005x56n_cyps]
C89  0.1uF  [capc1005x56n_cyps]
C90  0.22uF  [capc1005x56n_cyps]
C91  0.22uF  [capc1005x56n_cyps]
C92  0.22uF  [capc1005x56n_cyps]
C93  0.22uF  [capc1005x56n_cyps]
C94  0.22uF  [capc1005x56n_cyps]
C95  0.22uF  [capc1005x56n_cyps]
C96  2200pF  [C1808]
C97  0.22uF  [capc1005x56n_cyps]
C98  2200pF  [C1808]
J12  GSB4211311WEU  [AMPHENOL_GSB4211311WEU]
J13  0472720001  [MOLEX_47272-0001]
R58  4.7k  [resc1005x40n_pec]
R59  0E  [resc1005x40n_pec]
R60  0E  [resc1005x40n_pec]
R61  100K  [resc1005x40n_pec]
R62  0E  [resc1005x40n_pec]
R63  0E  [resc1005x40n_pec]
R64  0E  [resc1005x40n_pec]
R65  0E  [resc1005x40n_pec]
R66  0E  [resc1005x40n_pec]
R68  0E  [resc1005x40n_pec]
R70  0E  [resc1005x40n_pec]
R71  0E  [resc1005x40n_pec]
R74  10k  [resc1608x55n_pec]
R75  10k  [resc1608x55n_pec]
R76  10k  [resc1608x55n_pec]
R77  10k  [resc1608x55n_pec]
R78  10k  [resc1608x55n_pec]
R79  10k  [resc1608x55n_pec]
R80  200k  [resc1005x40n_pec]
R81  200k  [resc1005x40n_pec]
R82  200k  [resc1005x40n_pec]
R83  200k  [resc1005x40n_pec]
R84  10k  [resc1608x55n_pec]
R85  0E  [resc1608x55n_pec]
R88  1M  [resc1005x40n_pec]
R89  1M  [resc1005x40n_pec]
R90  100K  [resc1005x40n_pec]
R127  0E  [resc1005x40n_pec]
R128  0E  [resc1005x40n_pec]
R129  0E  [resc1005x40n_pec]
R130  0E  [resc1005x40n_pec]
R131  0E  [resc1005x40n_pec]
R132  0E  [resc1005x40n_pec]
R136  0E  [resc1608x55n_pec]
U6  DT1240-04LP@UDFN10  [UDFN50P100X250X60-10N]
U7  DT1240-04LP@UDFN10  [UDFN50P100X250X60-10N]
U8  PI3DPX1205A  [QFN40P400X600X80-41T475X275N]
sheet 09 DISPLAY PORT - P1
C99  1uF  [capc1005x56n_cyps]
C100  0.1uF  [capc1005x56n_cyps]
C101  0.22uF  [capc1005x56n_cyps]
C102  0.1uF  [capc1005x56n_cyps]
C103  0.1uF  [capc1005x56n_cyps]
C104  0.1uF  [capc1005x56n_cyps]
C105  0.1uF  [capc1005x56n_cyps]
C106  0.1uF  [capc1005x56n_cyps]
C107  0.1uF  [capc1005x56n_cyps]
C108  0.1uF  [capc1005x56n_cyps]
C109  0.22uF  [capc1005x56n_cyps]
C110  0.22uF  [capc1005x56n_cyps]
C111  0.22uF  [capc1005x56n_cyps]
C112  0.22uF  [capc1005x56n_cyps]
C113  0.22uF  [capc1005x56n_cyps]
C114  0.22uF  [capc1005x56n_cyps]
C115  0.22uF  [capc1005x56n_cyps]
C116  2200pF  [C1808]
C117  2200pF  [C1808]
J14  GSB4211311WEU  [AMPHENOL_GSB4211311WEU]
J15  0472720001  [MOLEX_47272-0001]
R91  0E  [resc1005x40n_pec]
R92  0E  [resc1005x40n_pec]
R93  4.7k  [resc1005x40n_pec]
R94  100K  [resc1005x40n_pec]
R95  0E  [resc1005x40n_pec]
R96  0E  [resc1005x40n_pec]
R97  0E  [resc1005x40n_pec]
R98  0E  [resc1005x40n_pec]
R99  0E  [resc1005x40n_pec]
R100  0E  [resc1005x40n_pec]
R101  0E  [resc1005x40n_pec]
R103  0E  [resc1005x40n_pec]
R104  0E  [resc1005x40n_pec]
R107  10k  [resc1608x55n_pec]
R108  10k  [resc1608x55n_pec]
R109  10k  [resc1608x55n_pec]
R110  10k  [resc1608x55n_pec]
R111  10k  [resc1608x55n_pec]
R112  10k  [resc1608x55n_pec]
R113  200k  [resc1005x40n_pec]
R114  200k  [resc1005x40n_pec]
R115  200k  [resc1005x40n_pec]
R116  200k  [resc1005x40n_pec]
R117  10k  [resc1608x55n_pec]
R118  0E  [resc1608x55n_pec]
R121  1M  [resc1005x40n_pec]
R122  1M  [resc1005x40n_pec]
R123  100K  [resc1005x40n_pec]
R124  0E  [resc1005x40n_pec]
R125  0E  [resc1005x40n_pec]
R126  0E  [resc1005x40n_pec]
R133  0E  [resc1005x40n_pec]
R134  0E  [resc1005x40n_pec]
R135  0E  [resc1608x55n_pec]
U9  DT1240-04LP@UDFN10  [UDFN50P100X250X60-10N]
U10  DT1240-04LP@UDFN10  [UDFN50P100X250X60-10N]
U11  PI3DPX1205A  [QFN40P400X600X80-41T475X275N]

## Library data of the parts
C1 C6 C8-C11 C13 = CAP_NP: CAP CER 0.1UF 10V X7R 0402; Manufacturer: AVX Corporation; Mfr_Name: AVX Corporation; Mfr_Part#: 0402ZC104KAT2A; RATED_VOLTAGE: 10V; Rating: 10V; SIGNAL_MODEL: DEFAULT_CAPACITOR_1pF_1_2; Temp_Coefficient: X7R; Tolerance: 10%; VOLTAGE: 10V
C2-C5 = CAP-NP_0: CAP CER 390PF 50V 5% X7R 0603; Manufacturer: Kemet; Mfr_Name: Kemet; Mfr_Part#: C0603C391J5RACTU; RATED_VOLTAGE: 10V; Temp_Coefficient: X7R; Tolerance: 5%; VOLTAGE: 50V
C7 = CAP-NP_0: CAP CER 4.7UF 16V X5R 0603; Manufacturer: Samsung Electro-Mechanics; Mfr_Name: Samsung Electro-Mechanics; Mfr_Part#: CL10A475KO8NNNC; RATED_VOLTAGE: 16V; Temp_Coefficient: X5R; Tolerance: 10%; VOLTAGE: 16V
C12 C14 C16 = CAP-NP_0: CAP CER 1UF 16V X7R 0603; Manufacturer: KEMET; Mfr_Name: KEMET; Mfr_Part#: C0603C105K4RACTU; RATED_VOLTAGE: 16V; Temp_Coefficient: X7R; Tolerance: 10%; VOLTAGE: 16V
C15 = CAPACITOR_NON-POL: CAP, CER, 0.1UF, 10%, X7R, 16V, 0402; Asm_Instruction: No Load; Cy_Part#: 510-60247-01; Mfr_Name: Wurth; Mfr_Part#: 885012205037; Tolerance: 10%; VOLTAGE: 16V
J1 = 1X5_100MIL_HDR_4: CONN HEADER 5POS 0.1 VERT KEYED; MFG Part number: 22232051; Manufacturer: Molex, LLC; Mfr_Name: Molex; Mfr_Part_Number: 22-23-2051; PART_NUMBER: 22232051
LED1 = LED_GREEN2_0603: LED GREENCLEAR 0603 SMD; Manufacturer: Lite-On Inc.; Manufacturer Part Num: 160-1183-6-ND; Mfr_Name: Lite-On Inc.; Mfr_Part#: LTST-C190GKT
R1 = RESISTOR: RES, 4.7K OHM, 5%, 100PPM, 1/16W, 0402; Cy_part#: 500-60095-01; Mfr_Name: Yageo; Mfr_Part#: RC0402JR-074K7L; Tolerance: 5%
R2 = RESD,0402,5%,1_32W,10K: RES SMD 330 OHM 5% 1/10W 0603; IPN: D66113-001; Manufacturer: Yageo; Mfg2: Yageo; Mfr_Name: Yageo; Mfr_Part#: RC0603JR-07330RL; Tolerance: 5%; Wattage: 1/10W
SW1 = SW_PUSH_NO_4-PIN: SW, TACTILE SWITCH, 4.2x3.2x2.5MM, 260GF; Cy_part#: 770-60033-01; Mfr_Name: Wurth
U1 = CYPM1322-97BZXI_9
C17 = CAP_TH_Rad_8mmDia_3_5mmPitch: CAP ALUM POLY 100UF 20% 35V SMD; Manufacturer: Nichicon; Mfr_Part#: RHS1V101MCN1GS; Voltage: 50V
C18 C19 C26 C27 C29 C31 C40 C41 C48 C49 C51 C53 = CAP-NP_0: CAP CER 1UF 16V X7R 0603; Alternate Manufacturer: TDK Corporation; Alternate Mfr Part #: C2012X5R1H106K125AC; Manufacturer: Murata Electronics; Mfr_Part#: GRM21BR61H106ME43L; Voltage: 50V
C20 C21 C25 C37 C42 C43 C47 C59 = CAP_NP: CAP CER 0.1UF 50V X7R 0603; Alternate Manufacturer: KEMET; Alternate Mfr Part #: C0603C104M5RAC7867; Manufacturer: Samsung Electro-Mechanics; Mfr_Part#: CL10B104KB8NNNL; Voltage, Tolerance: 50V, 20%
C22 C28 C32 C35 C44 C50 C54 C57 = CAP_NP: CAP CER 1UF 50V X5R 0603; Alternate Manufacturer: Samsung Electro-Mechanics; Alternate Mfr Part #: CL10A105KB8NNNC; Asm_Instruction: No Load; Manufacturer: TDK Corporation; Mfr_Part#: CGA3E3X5R1H105K080AB; Voltage, Tolerance: 50V, 10%
C23 C24 C45 C46 = CAP-NP_0: CAP CER 0.022UF 50V X7R 0603; Alternate Manufacturer: TDK Corporation; Alternate Mfr Part #: CGA3E2X7R1H223K080AA; Manufacturer: Samsung Electro-Mechanics; Mfr_Part#: CL10B223KB8WPNC
C30 = CAP_TH_Rad_8mmDia_3_5mmPitch: CAP ALUM POLY 100UF 20% 35V SMD; MFG Part number: RHS1V101MCN1GS; Manufacturer: Nichicon; Mfr_Name: Nichicon; Mfr_Part#: RHS1V101MCN1GS; Voltage: 35V
C33 C55 = CAP-NP_0: CAP CER 100PF 25V C0G/NP0 0603; Alternate Manufacturer: YAGEO; Alternate Mfr Part #: CC0603JRNPO8BN101; Manufacturer: KEMET; Mfr_Part#: C0603C101K3GAC7867; Voltage: 25V
C34 C56 C80 C99 = CAP-NP_0: CAP CER 1UF 16V X7R 0603; Alternate Manufacturer: Taiyo Yuden; Alternate Mfr Part #: EMK105BJ105KV-F; Manufacturer: Samsung Electro-Mechanics; Mfr_Part#: CL05A105KO5NNNC; Voltage: 16V
C36 C58 = CAP_NP: CAP CER 1UF 50V X5R 0603; Alternate Manufacturer: Samsung Electro-Mechanics; Alternate Mfr Part #: CL10A105KB8NNNC; Manufacturer: TDK Corporation; Mfr_Part#: CGA3E3X5R1H105K080AB; Voltage, Tolerance: 50V, 10%
C38 C60 = CAP-NP_0: CAP CER 10UF 50V X7R 1210; Alternate Manufacturer: TDK Corporation; Alternate Mfr Part #: CGA6P1X7R1N106K250AC; Manufacturer: Samsung Electro-Mechanics; Mfr_Part#: CL32B106KBJNNWE; Voltage: 50V
D1 D2 D4 D5 = BZX84C18_SOT_0: DIODE SCHOTTKY 30V 5A SOD128; Manufacturer: NXP Semiconductors
D3 D6 = BZX84C18_SOT_0: TVS DIODE 24VWM 50VC DO214AA; Manufacturer: STMicroelectronics
J2 J6 = CONN_JACK_PWR_2: CONN PWR JACK DC RIGHT ANGLE THROUGH HOLE; Cypress Part #: 720-60264-01; Manufaturer: Wurth electronics
J3 J5 = CON2_0: CONN HEADER VERT SGL 2POS GOLD; Cypress Part No: 710-60032-01; Manufacturer: 3M
J4 J7 = TERMINAL_BLOCK: TERM BLOCK PCB 2POS 5.0MM GREEN; Cypress Part #: 720-60276-01; Manufacturer: Phoenix Contact
L1 L2 = INDUCTOR: FIXED IND 4.7UH 11.5A 9.5MOHM SM; Manufacturer: Monolithic Power Systems Inc.; Mfr_Part#: MPL-AY1050-4R7
Q1-Q6 Q10 Q11 = BSC059N04LS_G_2: MOSFET N-CH 40V 17A TDSON; Manufacturer: Infineon Technologies; Mfr_Name: Infineon Technologies
R3 R16 = R: RES 3.3 OHM 1% 1/10W 0603; Manufacturer: YAGEO; Mfr_Part#: RC0603FR-073R3L
R4 R17 = R: RES 20 OHM 1% 1/10W 0603; Manufacturer: YAGEO; Mfr_Part#: RC0603FR-0720RL
R5 R6 R9 R18 R19 R22 R59 R60 R62-R66 R68 R70 R71 R85 R91 R92 R95-R101 R103 R104 R118 R124-R130 R147-R149 = R: RES 0.0 OHM 1/16W JUMP 0402 SMD; Manufacturer: Vishay Dale; Mfr_Part#: CRCW04020000Z0ED
R7 R21 = R: RES 100K OHM 1% 1/10W 0603; Alternate Manufacturer: Stackpole Electronics Inc; Alternate Mfr Part #: RMCF0603FG100K; Manufacturer: YAGEO; Mfr_Part#: RC0603FR-07100KL
R8 R20 = R: RES 140K OHM 1% 1/10W 0603; Manufacturer: YAGEO; Mfr_Part#: RC0603FR-07140KL
R10 R15 R23 R28 R77-R79 R107 R111 R112 R141-R144 = R: RES 10K OHM 1% 1/8W 0603; Alternate Manufacturer: Rohm Semiconductor; Alternate Mfr Part #: ESR03EZPF1002; Manufacturer: Stackpole Electronics Inc; Mfr_Part#: RNCP0603FTD10K0
R11 R24 = R: RES 0.0 OHM 1/16W JUMP 0402 SMD; Asm_Instruction: No Load
R12 R25 = Resistor_1206_Generic_SMD_4: 0.005 Ohms 1 %  1/2 W 1206 SMD; Manufacturer: Vishay Dale; Mfr_Part#: WSL12065L000FEA18; Package: 1206; Wattage: 1/2 W
R13 R14 R26 R27 R58 R93 = R: RES 4.7K OHM 1% 1/16W 0402; Alternate Manufacturer: TE Connectivity Passive Product; Alternate Mfr Part #: CRGCQ0402J4K7; Manufacturer: Stackpole Electronics Inc; Mfr_Part#: RMCF0402FT4K70
U2 U3 = MPQ4260_U1_0
DC_PWR1 USB_P_PWR_P1 USB_P_PWR_P2 V5P1 = TEST_POINT: TEST POINT PC MINI .040"D RED; Cypress Part No: 711-60001-01
C39 C52 = CAP_TH_Rad_8mmDia_3_5mmPitch: CAP ALUM POLY 100UF 20% 35V SMD; MFG Part number: RHS1V101MCN1GS; Manufacturer: Nichicon; Mfr_Name: Nichicon; Mfr_Part#: RHS1V101MCN1GS; Voltage: 55V
R145 = R: RES 976K OHM 1% 1/10W 0603; Alternate Manufacturer: Panasonic Electronic Components; Alternate Mfr Part #: ERJ-3EKF9763V; Manufacturer: YAGEO; Mfr_Part#: RC0603FR-07976KL
R146 = R: RES 182K OHM 1% 1/10W 0603; Alternate Manufacturer: Panasonic Electronic Components; Alternate Mfr Part #: ERJ-3EKF1823V; Manufacturer: YAGEO; Mfr_Part#: RC0603FR-07182KL
U12 = LTC4316_0
C61 C64 = 10uF-50V-10%-X5R-1206: CAP CER 4.7UF 50V X7R 1210; Cypress Part No: 510-60425-01; MFG Part number: GRJ32ER71H475KE11L; Manufacturer: Murata Electronics North America; Voltage: 50V
C62 C65 = CAP_NP: CAP CER 0.1UF 100V X7R 0603; MFG Part number: CL10B104KC8NNNC; Manufacturer: Samsung Electro-Mechanics; Voltage: 100V
C63 C66 C96 C98 C116 C117 = CAP_NP: CAP CER 2200PF 2KV 10% X7R 1808; Cypress Part No: 510-60319-01; MFG Part number: 202R29W222KV4E; Manufacturer: Johanson Dielectrics Inc.; Tolerance: 10%; VOLTAGE: 2KV
D7 D9 = BZX84C18_SOT_1: TVS DIODE 24V 38.9V DO214AA; Cypress Part No: 530-60094-01; DNP: DNP; Manufacturer: Vishay Semiconductor Diodes Division
D8 D10 = DIODE_ZENER: DIODE ZENER 10V 500MW SOD123F; MFG Part number: NZH10C,115; Manufacturer: Nexperia USA Inc.; Mfr_Name: Nexperia USA Inc.; Mfr_Part#: NZH10C,115
J8 J10 = USB-PD_TYPE-C_20: USB TYP C TP MNT DL RW SMT RECEP; DIGI-KEY PART NO: 670-2794-1-ND; Manufacturer: JAE Electronics; Price: 2.61
J9 J11 = TERMINAL_BLOCK: TERM BLOCK PCB 2POS 5.0MM GREEN; Cypress Part No: 720-60276-01; Manufacturer: Phoenix Contact
Q7 Q8 Q12 Q13 = SPP80P06P_H_1
Q9 Q14 = N-MOSFET_2N7002_SOT23_0: MOSFET N-CH 60V 0.115A SOT-23; Alternate Manufacturer: ON SEMICONDUCTOR; Alternate Part Number: 2V7002LT3G; Manufacturer: ON SEMICONDUCTOR
R29 R34 = RESISTOR: RES SMD 0.005 OHM 1% 2W 2512; DIGI-KEY PART NO: RHM.010AUCT-ND; MFG Part number: PMR100HZPFU5L0; Manufacturer: Rohm Semiconductor; Price: 0.77; TOLERANCE: 1%; WATT: 2W
R30 R35 R61 R90 R94 R123 = 10K-1_16W-5%-0603: RES SMD 100K OHM 1% 1/5W 0402; Cypress Part No: 500-60075-01; MFG Part number: RCS0402100KFKED; Manufacturer: Vishay Dale
R31 R36 = RESISTOR: RES SMD 5.1K OHM 1% 1/16W 0402; MFG Part number: RC0402FR-075K1L; Manufacturer: Yageo; Mfr_Name: Yageo; Mfr_Part#: RC0402FR-075K1L; Price: 0.1; TOLERANCE: 5%
R32 R37 = R: RES SMD 10K OHM 5% 1/16W 0402; MFG Part number: RC0402JR-0710KL; Manufacturer: Panasonic Electronic Components; Mfr_Name: Panasonic Electronic Components; Mfr_Part#: RC0402JR-0710KL; Price: 0.1; Tolerance: 5%
R33 R38 = 100K-1_16W-5%-0603: RES SMD 100K OHM 1% 1/10W 0603; ALTERNATE MANUFACTURER: Stackpole Electronics Inc.; ALTERNATE PART NUMBER: RMCF0603FT100K; Alternate Manufacturer_1: Yageo America; Alternate Part number_1: RC0603FR-07100KL; MFG Part number: ERJ-3EKF1003V; Manufacturer: PANASONIC ELECTRONIC COMPONENTS; Mfg1_PN: ERJ-3GEYJ104V; PART_NUMBER: ERJ-3GEYJ104V; Tolerance: 1%; Wattage: 1/10W
R131-R140 = R: RES 0.0 OHM 1/16W JUMP 0402 SMD; Asm_Instruction: No Load; Manufacturer: Vishay Dale; Mfr_Part#: CRCW04020000Z0ED
C67 C71-C78 = CAP-NP_0: CAP CER 1UF 16V X7R 0603
C68 C69 = CAP-NP_0: 1206; Manufacturer: TDK CORPORATION; Mfr_Part#: C3216X5R1V226M160AC
C70 C79 = CAP-NP_0: CAP CER 1UF 16V X7R 0603; Asm_Instruction: No Load
D11 D13 D14 = BZX84C18_SOT_0: DIODE SCHOTTKY 30V 5A SOD128; Cypress Part No: 530-60089-01; Manufacturer: NXP Semiconductors
D12 = BZX84C18_SOT_0: TVS DIODE 24VWM 50VC DO214AA; Cypress Part No: 530-60092-01; Manufacturer: STMicroelectronics
L3 = INDUCTOR: FIXED IND 3.3UH 8A 20.9 MOHM SMD; Cost: .01; Manufacturer: Vishay Dale; Tolerance: NA; Voltage: NA
L4 = INDUCTOR: FIXED IND 1.5UH 3.8A 32 mOHM SMD; Cost: .01; Manufacturer: Vishay Dale; Tolerance: NA; Voltage: NA
LED2 LED3 = LED_GREEN2_0: LED GREEN CLEAR 0603 SMD; Cypress Part No: 534-60005-01; MFG Part number: LTST-C190GKT; Manufacturer: Lite-On Inc.
R39-R42 R45 R46 R48 R50-R57 = R
R43 R44 R47 R49 R80-R83 R113-R116 = R: Asm_Instruction: No Load
U4 = mp8759_0: IC SYNC BUCK CONVERTER 8A 26V; Manufacturer: MPS
U5 = MP2162_1: IC REG BUCK ADJ 2A SYNC QFN; Manufacturer: MPS
C81 C83-C89 C100 C102-C108 = CAP-NP_0: CAP CER 0.1UF 10V 10% X7R 0402; Alternate Manufacturer: Samsung Electro-Mechanics; Alternate Mfr Part #: CL05B104KP5NNNC; Manufacturer: TDK Corporation; Mfr_Part#: C1005X7R1A104K050BB; Voltage: 10V
C82 C90-C95 C97 C101 C109-C115 = CAP-NP_0: CAP CER 1UF 16V X7R 0603; Manufacturer: Yageo; Mfr_Part#: CC0402KRX7R7BB224; Voltage: 16V
J12 J14 = USB3_TYPE-B_0: Connector Receptacle USB TypeB 3.1, Super Speed 9 Position Through Hole, Right Angle, Horizontal; DIGI-KEY PART NO: GSB4211311WEU-ND; Manufacturer: Amphenol Commercial Products; Price: 2.54
J13 J15 = DISPLAY_PORT_CONN_0: Connector Receptacle DisplayPort 20 Position Surface Mount, Right Angle, Horizontal; DIGI-KEY PART NO: WM19271CT-ND; MFG Part number: 472720001; Manufacturer: Molex, LLC; Price: 5.3
R74-R76 R84 R108-R110 R117 = R: RES 10K OHM 1% 1/8W 0603; Alternate Manufacturer: Rohm Semiconductor; Alternate Mfr Part #: ESR03EZPF1002; Asm_Instruction: No Load; Manufacturer: Stackpole Electronics Inc; Mfr_Part#: RNCP0603FTD10K0
R88 R89 R121 R122 = R: RES 1M OHM 1% 1/16W 0402; Alternate Manufacturer: TE Connectivity Passive Product; Alternate Mfr Part #: CRGCQ0402J1M0; Manufacturer: Stackpole Electronics Inc; Mfr_Part#: RMCF0402FT1M00
U6 U7 U9 U10 = DT1240-04LP-UDFN10: TVS DIODE 5.5VWM 11VC DFN; MFG Part Number: DT1240-04LP; Manufacturer: Diodes Incorporated
U8 U11 = PI3DPX1205AZLBE-TQFN40_0: 10G MUX; MFG Part Number: PI3DPX1205AZLBE; Manufacturer: Pericom

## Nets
AGND1: C1.1 C2.1 C3.1 C4.1 C5.1 C6.1 C7.1 C8.1 C9.1 C10.1 C11.1 C12.1 C13.1 C14.1 C15.1 C16.1 C17.2 C18.1 C19.1 C20.2 C21.2 C22.2 C25.2 C26.1 C27.1 C28.2 C33.1 C34.1 C35.2 C36.2 C37.2 C38.1 C39.2 C40.1 C41.1 C42.2 C43.2 C44.2 C47.2 C48.1 C49.1 C50.2 C55.1 C56.1 C57.2 C58.2 C59.2 C60.1 C68.1 C69.1 C71.1 C72.1 C73.1 C74.1 C75.1 C76.1 C77.1 C78.1 D3.A(ANODE) D6.A(ANODE) D12.A(ANODE) J1.2 J2.2 J2.3 J4.1 J6.2 J6.3 J7.1 J9.2 J11.2 LED1.K(CATHODE) LED2.K(CATHODE) LED3.K(CATHODE) Q9.2(SOURCE) Q14.2(SOURCE) R10.2 R11.1 R12.2 R23.2 R24.1 R25.2 R33.1 R38.1 R47.2 R49.2 R50.2 R57.2 R147.1 SW1.3 SW1.4 U1.F8(VSS) U1.F10(VSS) U1.F12(VSS) U1.H8(VSS) U1.H10(VSS) U1.K8(VSS) U1.K10(VSS) U2.5(ISEN-) U2.11(AGND) U2.12(PGND) U2.15(PGND1) U3.5(ISEN-) U3.11(AGND) U3.12(PGND) U3.15(PGND1) U4.2(PGND) U4.10(AGND) U5.3(AGND) U5.5(PGND) U12.1(GND)
GND0: C29.1 C30.2 C31.1 C35.1 C61.1 C63.2 C80.1 C83.1 C84.1 C85.1 C86.1 C87.1 C88.1 C96.2 C98.2 D7.A(ANODE) J8.A1(GND_1) J8.A12(GND_2) J8.B1(GND_3) J8.B12(GND_4) J12.4(GND) J12.7(GND_DRAIN) J13.2(GND_1) J13.5(GND_2) J13.8(GND_3) J13.11(GND_4) J13.16(GND_5) J13.19(RETURN) R12.1 R30.2 R61.2 R77.1 R78.1 R79.1 R80.1 R81.1 R82.1 R83.1 R88.1 R89.1 R90.2 U2.6(ISEN+) U6.3(VSS) U6.8(VSS) U7.3(VSS) U7.8(VSS) U8.41(HGND)
GND1: C51.1 C52.2 C53.1 C57.1 C64.1 C66.2 C99.1 C102.1 C103.1 C104.1 C105.1 C106.1 C107.1 C116.2 C117.2 D9.A(ANODE) J10.A1(GND_1) J10.A12(GND_2) J10.B1(GND_3) J10.B12(GND_4) J14.4(GND) J14.7(GND_DRAIN) J15.2(GND_1) J15.5(GND_2) J15.8(GND_3) J15.11(GND_4) J15.16(GND_5) J15.19(RETURN) R25.1 R35.2 R94.2 R110.1 R111.1 R112.1 R113.1 R114.1 R115.1 R116.1 R121.1 R122.1 R123.2 U3.6(ISEN+) U9.3(VSS) U9.8(VSS) U10.3(VSS) U10.8(VSS) U11.41(HGND)
GND_EARTH0: C63.1 J8.SH_1(SH1) J8.SH_2(SH2) J8.SH_3(SH3) J8.SH_4(SH4) J8.SH_5(SH5) J8.SH_6(SH6) R30.1
V3P3: C77.2 C78.2 C83.2 C84.2 C85.2 C86.2 C87.2 C88.2 C102.2 C103.2 C104.2 C105.2 C106.2 C107.2 R13.1 R14.1 R15.1 R26.1 R27.1 R28.1 R52.2 R55.1 R58.2 R74.2 R75.2 R76.2 R84.2 R93.2 R107.2 R108.2 R109.2 R117.2 R141.2 R142.2 R143.2 R144.2 R145.1 U8.10(VDD33) U8.14(VDD33) U8.17(VDD33) U8.26(VDD33) U8.32(VDD33) U8.35(VDD33) U8.38(VDD33) U11.10(VDD33) U11.14(VDD33) U11.17(VDD33) U11.26(VDD33) U11.32(VDD33) U11.35(VDD33) U11.38(VDD33) U12.4(VCC) U12.5(EN)
V5P0: C12.2 C13.2 C14.2 C16.2 R42.2 R46.1 R51.1 U1.B14(VSYS) U1.L1(VCONN_P1) U1.L2(VCONN_P1) U1.L14(VCONN_P0) U1.L15(VCONN_P0) V5P1.1
VBUS_C_CTRL_P0: Q9.1(GATE) R33.2 U1.K4(P1.3)
VBUS_C_CTRL_P1: Q14.1(GATE) R38.2 U1.B9(P7.6)
VBUS_IN_CTRL_SRC_P0: Q5.4(GATE) U1.P14(VBUS_IN_CTRL__P0)
VBUS_IN_CTRL_SRC_P1: Q10.4(GATE) U1.P2(VBUS_IN_CTRL__P1)
VBUS_OUT_CTRL_SRC_P0: Q6.4(GATE) U1.P15(VBUS_OUT_CTRL_P0)
VBUS_OUT_CTRL_SRC_P1: Q11.4(GATE) U1.P1(VBUS_OUT_CTRL)
VCCD: C1.2 U1.D10(VCCD)
VDDA: C6.2 C7.2 C8.2 C9.2 C10.2 C11.2 J1.1 R1.2 U1.B8(VDDIO) U1.D6(VDDA) U1.D8(VDDD) U1.F6(VDDA) U1.H12(VDDIO)
VIN_BARREL_P0: C17.1 C18.2 C19.2 C20.1 C21.1 C22.1 C36.1 C37.1 C38.2 D1.C(CATHODE) D2.C(CATHODE) D3.C(CATHODE) J3.2 J5.2 Q1.5(DRAIN1) Q1.6(DRAIN2) Q1.7(DRAIN3) Q1.8(DRAIN4) R7.1 U2.20(VIN)
VIN_BARREL_P1: C39.1 C40.2 C41.2 C42.1 C43.1 C44.1 C58.1 C59.1 C60.2 D4.C(CATHODE) D5.C(CATHODE) D6.C(CATHODE) J3.1 J5.1 Q3.5(DRAIN1) Q3.6(DRAIN2) Q3.7(DRAIN3) Q3.8(DRAIN4) R21.1 U3.20(VIN)
VIN_DC: D11.A(ANODE)
ALT_REG_P0: R15.2 U1.A2(P2.0) U2.3(ALT)
ALT_REG_P1: R28.2 U1.B2(P2.1) U3.3(ALT)
AUXN_DP0: J13.17(AUX_CH_N) R128.1 R131.1
AUXN_DP1: J15.17(AUX_CH_N) R126.1 R133.1
AUXN_PMG1S3_P0: R131.2 U1.P11(AUX_P_P0)
AUXN_PMG1S3_P1: R133.2 U1.M6(AUX_N_P1)
AUXP_DP0: J13.15(AUX_CH_P) R127.1 R132.1
AUXP_DP1: J15.15(AUX_CH_P) R125.1 R134.1
AUXP_PMG1S3_P0: R132.2 U1.P9(AUX_N_P0)
AUXP_PMG1S3_P1: R134.2 U1.M4(AUX_P_P1)
CC1_P0: C2.2 J8.A5(CC1) U1.N14(CC1_P0) U1.N15(CC1_P0)
CC1_P1: C5.2 J10.A5(CC1) U1.N1(CC1_P1) U1.N2(CC1_P1)
CC2_P0: C3.2 J8.B5(CC2) U1.J14(CC2_P0) U1.J15(CC2_P0)
CC2_P1: C4.2 J10.B5(CC2) U1.J1(CC2_P1) U1.J2(CC2_P1)
CSN_P0: Q5.1(SOURCE1) Q5.2(SOURCE2) Q5.3(SOURCE3) R29.2 U1.A15(CSN_P0) U1.R14(VBUS_IN_NGDO__P0)
CSN_P1: Q10.1(SOURCE1) Q10.2(SOURCE2) Q10.3(SOURCE3) R34.2 U1.C14(CSN_P1) U1.R2(VBUS_IN_NGDO__P1)
DM_TYPEC_P0: J8.A7(D-) J8.B7(D-) J12.2(D-)
DM_TYPEC_P1: J10.A7(D-) J10.B7(D-) J14.2(D-)
DP_TYPEC_P0: J8.A6(D+) J8.B6(D+) J12.3(D+)
DP_TYPEC_P1: J10.A6(D+) J10.B6(D+) J14.3(D+)
EARTH_GND1: C66.1 J10.SH_1(SH1) J10.SH_2(SH2) J10.SH_3(SH3) J10.SH_4(SH4) J10.SH_5(SH5) J10.SH_6(SH6) R35.1
EARTH_GND2: C96.1 J12.SH1 J12.SH2 R61.1
EARTH_GND3: C98.1 J13.SH1 J13.SH2 J13.SH3 J13.SH4 R90.1
EARTH_GND4: C116.1 J14.SH1 J14.SH2 R94.1
EARTH_GND5: C117.1 J15.SH1 J15.SH2 J15.SH3 J15.SH4 R123.1
EN_REG_P0: R7.2 R11.2 U2.17(EN)
EN_REG_P1: R21.2 R24.2 U3.17(EN)
FET_GATE0: C62.2 D8.2(ANODE) Q7.1(G) Q8.1(G) R31.1 R32.2
FET_GATE1: C65.2 D10.2(ANODE) Q12.1(G) Q13.1(G) R36.1 R37.2
FET_SRC0: D8.1(CATHODE) Q7.3(S) Q8.3(S) R32.1
FET_SRC1: D10.1(CATHODE) Q12.3(S) Q13.3(S) R37.1
HP_DET_DP_P0: R136.2 U1.B7(P2.6)
HP_DET_DP_P1: R135.2 U1.A8(P2.7)
I2C_SCL: R144.1 R148.1 U1.E15(P4.0) U8.6(SCL) U11.6(SCL) U12.10(SCLIN)
I2C_SCL_REG_P0: R13.2 R148.2 U2.1(SCL)
I2C_SCL_REG_P1: R26.2 R142.1 U3.1(SCL) U12.9(SCLOUT)
I2C_SDA: R143.1 R149.1 U1.D12(P4.1) U8.5(SDA) U11.5(SDA) U12.7(SDAIN)
I2C_SDA_REG_P0: R14.2 R149.2 U2.2(SDA)
I2C_SDA_REG_P1: R27.2 R141.1 U3.2(SDA) U12.8(SDAOUT)
IMON_REG_P0: C33.2 U2.16(IMON)
IMON_REG_P1: C55.2 U3.16(IMON)
IN_HPD_DP0: R84.1 R85.2 U8.25(IN_HPD)
IN_HPD_DP1: R117.1 R118.2 U11.25(IN_HPD)
LED: R2.2 U1.B1(P3.3)
M0+_P0: J13.12(ML_LANE_0P) R64.1
M0+_P1: J15.12(ML_LANE_0P) R97.1
M0-_P0: J13.10(ML_LANE_0N) R65.1
M0-_P1: J15.10(ML_LANE_0N) R98.1
M1+_P0: J13.9(ML_LANE_1P) R62.1
M1+_P1: J15.9(ML_LANE_1P) R95.1
M1-_P0: J13.7(ML_LANE_1N) R63.1
M1-_P1: J15.7(ML_LANE_1N) R96.1
M2+_P0: J13.6(ML_LANE_2P) R68.1
M2+_P1: J15.6(ML_LANE_2P) R101.1
M2-_P0: J13.4(ML_LANE_2N) R66.1
M2-_P1: J15.4(ML_LANE_2N) R99.1
M3+_P0: J13.3(ML_LANE_3P) R71.1
M3+_P1: J15.3(ML_LANE_3P) R104.1
M3-_P0: J13.1(ML_LANE_3N) R70.1
M3-_P1: J15.1(ML_LANE_3N) R103.1
PMG1S3_SWD_CLK: J1.4 U1.P3(P1.1)
PMG1S3_SWD_IO: J1.5 U1.R3(P1.2)
RX1+_P0: C97.1 J8.B11(RX1+) R82.2 U7.5(I/O4) U7.6(NC4)
RX1+_P1: C115.1 J10.B11(RX1+) R115.2 U10.5(I/O4) U10.6(NC4)
RX1-_P0: C95.1 J8.B10(RX1-) R83.2 U7.4(I/O3) U7.7(NC3)
RX1-_P1: C114.1 J10.B10(RX1-) R116.2 U10.4(I/O3) U10.7(NC3)
RX2+_P0: C91.1 J8.A11(RX2+) R80.2 U6.2(I/O2) U6.9(NC2)
RX2+_P1: C110.1 J10.A11(RX2+) R113.2 U9.2(I/O2) U9.9(NC2)
RX2-_P0: C92.1 J8.A10(RX2-) R81.2 U6.1(I/O1) U6.10(NC1)
RX2-_P1: C111.1 J10.A10(RX2-) R114.2 U9.1(I/O1) U9.10(NC1)
SBU1_P0: J8.A8(SBU1) R129.2 R138.2
SBU1_P1: J10.A8(SBU1) R100.2 R140.2
SBU1_PMG1S3_P0: R137.1 U1.R13(P6.3/SBU1_P0)
SBU1_PMG1S3_P1: R139.1 U1.R5(P6.0/SBU1_P1)
SBU2_P0: J8.B8(SBU2) R130.2 R137.2
SBU2_P1: J10.B8(SBU2) R124.2 R139.2
SBU2_PMG1S3_P0: R138.1 U1.P13(P6.2/SBU2_P0)
SBU2_PMG1S3_P1: R140.1 U1.P5(P6.1/SBU2_P1)
TX1+_P0: C94.1 J8.A2(TX1+) U7.2(I/O2) U7.9(NC2)
TX1+_P1: C113.1 J10.A2(TX1+) U10.2(I/O2) U10.9(NC2)
TX1-_P0: C93.1 J8.A3(TX1-) U7.1(I/O1) U7.10(NC1)
TX1-_P1: C112.1 J10.A3(TX1-) U10.1(I/O1) U10.10(NC1)
TX2+_P0: C82.1 J8.B2(TX2+) U6.5(I/O4) U6.6(NC4)
TX2+_P1: C101.1 J10.B2(TX2+) U9.5(I/O4) U9.6(NC4)
TX2-_P0: C90.1 J8.B3(TX2-) U6.4(I/O3) U6.7(NC3)
TX2-_P1: C109.1 J10.B3(TX2-) U9.4(I/O3) U9.7(NC3)
TYPE-C-VBUS_P0: C61.2 C62.1 D7.C(CATHODE) J8.A4(VBUS_1) J8.A9(VBUS_2) J8.B4(VBUS_3) J8.B9(VBUS_4) Q6.1(SOURCE1) Q6.2(SOURCE2) Q6.3(SOURCE3) Q8.2(D1) Q8.4(D2) U1.H15(VBUS_C_P0) U1.R15(VBUS_OUT_NGDO_P0)
TYPE-C-VBUS_P1: C64.2 C65.1 D9.C(CATHODE) J10.A4(VBUS_1) J10.A9(VBUS_2) J10.B4(VBUS_3) J10.B9(VBUS_4) Q11.1(SOURCE1) Q11.2(SOURCE2) Q11.3(SOURCE3) Q13.2(D1) Q13.4(D2) U1.H14(VBUS_C_P1) U1.R1(VBUS_OUT_NGDO_P1)
USB2_VBUS_P0: C80.2 J12.1(VBUS)
USB2_VBUS_P1: C99.2 J14.1(VBUS)
USB_C_PWR_P0: D13.A(ANODE) J9.1 Q7.2(D1) Q7.4(D2)
USB_C_PWR_P1: D14.A(ANODE) J11.1 Q12.2(D1) Q12.4(D2)
USB_P_PWR_P0: C25.1 C26.2 C27.2 C28.1 C29.2 C30.1 C31.2 Q2.5(DRAIN1) Q2.6(DRAIN2) Q2.7(DRAIN3) Q2.8(DRAIN4) R3.1 R4.1 R29.1 U1.B15(CSP_P0) USB_P_PWR_P1.1
USB_P_PWR_P1: C47.1 C48.2 C49.2 C50.1 C51.2 C52.1 C53.2 Q4.5(DRAIN1) Q4.6(DRAIN2) Q4.7(DRAIN3) Q4.8(DRAIN4) R16.1 R17.1 R34.1 U1.C15(CSP_P1) USB_P_PWR_P2.1
XRES: C15.2 J1.3 R1.1 SW1.1 SW1.2 U1.E14(XES)
N15529403: D11.C(CATHODE) D13.C(CATHODE) D14.C(CATHODE) R39.1
N15529415: C68.2 C69.2 D12.C(CATHODE) DC_PWR1.1 R39.2 R41.1 U4.1(VIN)
N15529515: R48.1 U4.9(VCC)
N15529591: C67.1 L3.1 R43.1 U4.7(SW)
N15529603: C70.1 C71.2 C72.2 C73.2 C74.2 L3.2 R42.1 R45.1 U4.5(OUT)
N15529707: C70.2 R43.2 R44.1
N15529767: R41.2 R47.1 U4.12(EN)
N15529891: R48.2 U4.3(PG)
N15529927: R44.2 R45.2 R50.1 U4.11(FB)
N15529939: R49.1 U4.6(MODE)
N15530225: C75.2 C76.2 R51.2 R53.1 R54.1 U5.7(VIN)
N15530257: C79.1 L4.2 R52.1 R56.1 U5.4(OUT)
N15530453: LED3.A(ANODE) R55.2
N15530457: R54.2 U5.1(EN)
N15530495: R53.2 U5.8(PG)
N15530519: C79.2 R56.2 R57.1 U5.2(FB)
N15534804: C24.1 L1.1 Q1.1(SOURCE1) Q1.2(SOURCE2) Q1.3(SOURCE3) U2.14(SW1)
N15534820: C23.2 L1.2 Q2.1(SOURCE1) Q2.2(SOURCE2) Q2.3(SOURCE3) U2.13(SW2)
N15534920: D2.A(ANODE) J2.1
N15535392: C24.2 R5.1
N15535412: C23.1 R6.2
N15535444: Q1.4(GATE) U2.18(HG1)
N15535480: Q2.4(GATE) U2.9(HG2)
N15535520: R3.2 U2.7(VOUT)
N15535524: C32.1 R4.2 R8.1
N15535590: R5.2 U2.19(BST1)
N15535594: R6.1 U2.8(BST2)
N15535736: C32.2 R8.2 R9.2 R10.1
N15535878: D1.A(ANODE) J4.2
N15535972: C34.2 U2.10(VCC)
N15571096: C89.2 J12.6(STDB_SSTX+)
N15571104: C81.2 J12.5(STDB_SSTX-)
N15571266: R58.1 U8.29(EN)
N15571292: J12.9(STDB_SSRX+) R59.1
N15571312: R59.2 U8.28(SSTXP)
N15571334: J12.8(STDB_SSRX-) R60.1
N15571354: R60.2 U8.27(SSTXN)
N15571392: C89.1 U8.24(SSRXP)
N15571430: C81.1 U8.23(SSRXN)
N15571434: C82.2 U8.20(TX2P)
N15571474: C90.2 U8.19(TX2N)
N15571514: C91.2 U8.16(RX2P)
N15571554: C92.2 U8.15(RX2N)
N15571606: C93.2 U8.12(TX1N)
N15571654: R62.2 U8.30(DP1P)
N15571658: C94.2 U8.11(TX1P)
N15571706: R63.2 U8.31(DP1N)
N15571710: C95.2 U8.8(RX1N)
N15571758: R64.2 U8.33(DP0P)
N15571762: C97.2 U8.7(RX1P)
N15571794: R65.2 U8.34(DP0N)
N15571846: R66.2 U8.36(DP2N)
N15571850: R129.1 U8.4(AUXSBU1)
N15571974: R68.2 U8.37(DP2P)
N15571978: R130.1 U8.3(AUXSBU2)
N15572008: R70.2 U8.39(DP3N)
N15572024: R71.2 U8.40(DP3P)
N15572028: R76.1 R79.2 U8.18(A2)
N15572068: R75.1 R78.2 U8.13(A1)
N15572104: R127.2 U8.1(AUXP)
N15572108: R74.1 R77.2 U8.9(A0)
N15572142: R128.2 U8.2(AUXN)
N15572412: J13.18(HotPlugDetect) R85.1 R136.1
N15577674: Q5.5(DRAIN1) Q5.6(DRAIN2) Q5.7(DRAIN3) Q5.8(DRAIN4) Q6.5(DRAIN1) Q6.6(DRAIN2) Q6.7(DRAIN3) Q6.8(DRAIN4)
N15632440: Q10.5(DRAIN1) Q10.6(DRAIN2) Q10.7(DRAIN3) Q10.8(DRAIN4) Q11.5(DRAIN1) Q11.6(DRAIN2) Q11.7(DRAIN3) Q11.8(DRAIN4)
N15644189: C108.2 J14.6(STDB_SSTX+)
N15644197: C100.2 J14.5(STDB_SSTX-)
N15644371: R93.1 U11.29(EN)
N15644403: J14.9(STDB_SSRX+) R91.1
N15644423: R91.2 U11.28(SSTXP)
N15644479: J14.8(STDB_SSRX-) R92.1
N15644499: R92.2 U11.27(SSTXN)
N15644535: C108.1 U11.24(SSRXP)
N15644655: C100.1 U11.23(SSRXN)
N15644659: C101.2 U11.20(TX2P)
N15644685: C109.2 U11.19(TX2N)
N15644735: C110.2 U11.16(RX2P)
N15644785: C111.2 U11.15(RX2N)
N15644843: C112.2 U11.12(TX1N)
N15644913: R95.2 U11.30(DP1P)
N15644917: C113.2 U11.11(TX1P)
N15644965: R96.2 U11.31(DP1N)
N15644969: C114.2 U11.8(RX1N)
N15645039: R97.2 U11.33(DP0P)
N15645043: C115.2 U11.7(RX1P)
N15645099: R98.2 U11.34(DP0N)
N15645165: R99.2 U11.36(DP2N)
N15645169: R100.1 U11.4(AUXSBU1)
N15645251: R101.2 U11.37(DP2P)
N15645255: R124.1 U11.3(AUXSBU2)
N15645299: R103.2 U11.39(DP3N)
N15645323: R104.2 U11.40(DP3P)
N15645327: R109.1 R112.2 U11.18(A2)
N15645375: R108.1 R111.2 U11.13(A1)
N15645425: R125.2 U11.1(AUXP)
N15645429: R107.1 R110.2 U11.9(A0)
N15645545: R126.2 U11.2(AUXN)
N15645993: J15.18(HotPlugDetect) R118.1 R135.1
N15651442: D4.A(ANODE) J6.1
N15651648: D5.A(ANODE) J7.2
N15653560: C45.1 L2.1 Q3.1(SOURCE1) Q3.2(SOURCE2) Q3.3(SOURCE3) U3.14(SW1)
N15653572: C46.2 L2.2 Q4.1(SOURCE1) Q4.2(SOURCE2) Q4.3(SOURCE3) U3.13(SW2)
N15653858: C45.2 R18.1
N15653878: C46.1 R19.1
N15654060: Q3.4(GATE) U3.18(HG1)
N15654064: Q4.4(GATE) U3.9(HG2)
N15654092: R16.2 U3.7(VOUT)
N15654096: C54.1 R17.2 R20.1
N15654272: C54.2 R20.2 R22.2 R23.1
N15654444: C56.2 U3.10(VCC)
N15702200: R145.2 R146.1 U12.3(XORL)
N15702204: R146.2 R147.2 U12.2(XORH)
N15706282: Q9.3(DRAIN) R31.2
N15706776: R9.1 U2.4(FB)
N15707165: LED1.A(ANODE) R2.1
N15707516: R18.2 U3.19(BST1)
N15707517: R19.2 U3.8(BST2)
N15707518: R22.1 U3.4(FB)
N15707772: Q14.3(DRAIN) R36.2
N15707984: C67.2 R40.1
N15707985: LED2.A(ANODE) R46.2
N15707986: R40.2 U4.8(BST)
N15707987: L4.1 U5.6(SW)
N15708362: J15.13(CONFIG1) R121.2
N15708363: J15.14(CONFIG2) R122.2
N15708778: J13.14(CONFIG2) R89.2
N15708779: J13.13(CONFIG1) R88.2

Not connected (* = marked no-connect by the designer): J13 20(DP_PWR)*; J15 20(DP_PWR)*; U1 A1(P3.0)* A3(P2.2)* A5(P2.5)* A7(P2.4)* A9(P7.5)* A11(USBDM)* A13(USBDP)* A14(P7.2)* B3(P3.1)* B5(P2.3)* B11(P7.4)* B13(P7.3)* C1(P3.7)* C2(P3.2)* D4(P3.4)* E1(P5.1)* E2(P3.6)* F4(P3.5)* G1(P5.4)* G2(P5.0)* G14(P7.1)* G15(P7.0)* H1(P5.3)* H2(P1.0)* H4(P5.5)* H6(P5.2)* K6(P0.3/DBG2_P1)* K12(P1.6)* M8(P0.5/DBG1_P0)* M10(P1.4)* M12(P1.5)* P7(P0.2/DBG1_P1)* P8(P0.4/DBG2_P0)* R7(P0.1/LSTX_P1)* R8(P0.0/LSRX_P1)* R9(P0.6/LSTX_P0)* R11(P0.7/LSRX_P0)*; U4 4(NC)*; U8 21(DCI_DAT)* 22(DCI_CLK)*; U11 21(DCI_DAT)* 22(DCI_CLK)*; U12 6(READY)*

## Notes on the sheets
sheet 1
- PMG1-S3 DUAL PORT (CYPM1322) DRP REFERENCE DESIGN
- CONTENTS
- PAGE
- DESCRIPTION
- 01
- TABLE AND CONTENTS
- 02
- CYPM1322-97BZXI - PMG1S3
- 03
- PD REGULATOR - P0
- 04
- PD REGULATOR - P1
- 05
- PROVIDER & CONSUMER PATHS-P0
- 06
- PROVIDER & CONSUMER PATHS-P1
- 07
- STEP DOWN REGULATORS
- 08
- DISPLAY PORT- P0
- 09
- DISPLAY PORT- P1
sheet 2
- CYPM1322-97BZXI - 97BGA
- CYPM1322-97BZXI - 97BGA
- DECOUPLING CAPACITORS
- SWD PROGRAMMING HEADER
- RESET BUTTON
- Note: Place decaps close to IC pin before via.
- VSYS AND VCONN_SRC
- USER LED
- If = 15mA
sheet 3
- PD REGULTOR - PORT-0
- I2C SLAVE ADDRESS: 67H
- NC- Default
- J1 - 24V DC Recommended for SPR (<20V, 5A)
- 1-2: Single external power input
- J2 - 50V DC Recommended for SPR & EPR (up to 48V)
sheet 4
- PD REGULTOR - PORT-1
- I2C SLAVE ADDRESS: 65H
- (Using Address Translator)
- I2C LEVEL TRANSLATOR
- ADDR IN:65H
- ADDR IN:67H
- Note:
  I2C level translator is not
  required if 2 different I2C buses
  are connected to PD regulators
- J3 - 24V DC Recommended for SPR (<20V, 5A)
- J4 - 50V DC Recommended for SPR & EPR (up to 48V)
sheet 5
- SPR Source
- 5V,9V,15V,20V / 5A
- TYPE-C CONNECTOR - PORT0
- EPR Source
- 28V / 5A
- PROVIDER PATH LOAD SWITCH - PORT0
- SPR Sink 5V - 20V
- EPR Sink 28V
- CONSUMER PATH LOAD SWITCH - PORT0
sheet 6
- SPR Source
- 5V,9V,15V,20V / 5A
- TYPE-C CONNECTOR - PORT1
- EPR Source
- 28V / 5A
- PROVIDER PATH LOAD SWITCH - PORT1
- SPR Sink 5V - 20V
- EPR Sink 28V
- CONSUMER PATH LOAD SWITCH - PORT1
sheet 7
- DC/DC CONVERTER 5V,2.5A
- Step-Down Regulator - 3.3V/1.5A
sheet 8
- ESD DT1240A-04LP
- Note: Place these ESD diodes close as possible to Type-C connector
- For I2C
  Address
- I2C Slave Addess 7 BIT :  0x50
sheet 9
- ESD DT1240A-04LP
- Note: Place these ESD diodes close as possible to Type-C connector
- For I2C
  Address
- I2C Slave Addess 7 BIT :  0x51
